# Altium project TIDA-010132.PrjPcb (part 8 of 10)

## Sheet AFE2-SERDES.SchDoc
size 431 x 279 mm; Date: Not shown in title block; ApprovedBy: Not shown in title block; CheckedBy: Not shown in title block; Author: Not shown in title block; CompanyName: Not shown in title block; DrawnBy: Avinash N; Engineer: Not shown in title block; Organization: Not shown in title block; Address1: Not shown in title block; Address2: Not shown in title block; Address3: Not shown in title block; Address4: Not shown in title block; DocumentNumber: 1; Revision: Use project parameter SCH_Rev; SheetNumber: 19; SheetTotal: 32; PageSetup: Record=PageOptions¦CenterHorizontal=True¦CenterVertical=True¦PrintScale=1.00¦XCorrection=1.00¦YCorrection=1.00¦PrintKind=0¦BorderSize=5000000¦LeftOffset=0¦BottomOffset=0¦Orientation=2¦PaperLength=1000¦PaperWidth=1000¦Scale=100¦PaperSource=15¦PrintQuality=600¦MediaType=1¦DitherType=10¦PaperKind=Letter¦PrintScaleMode=1
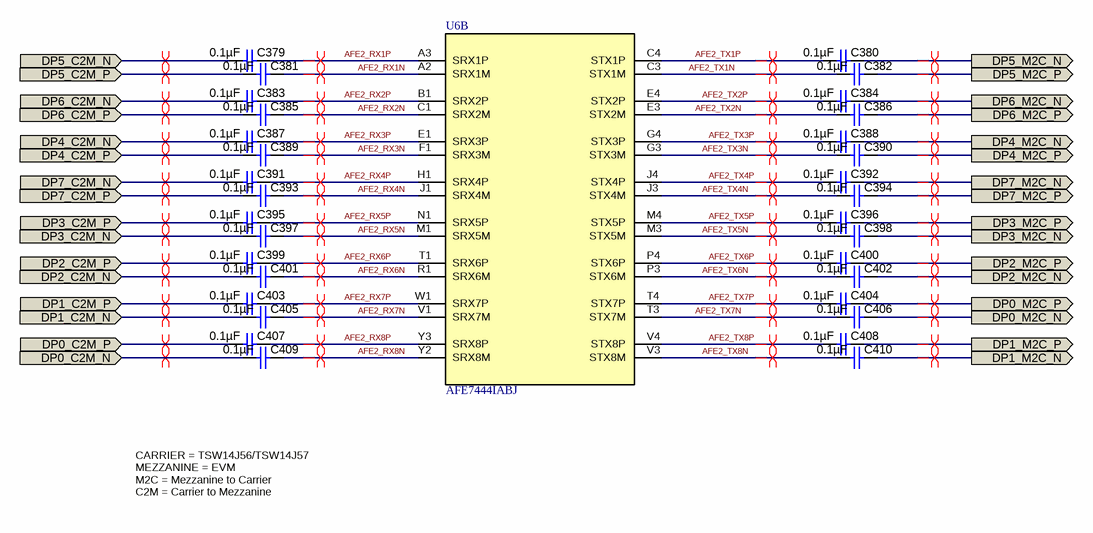
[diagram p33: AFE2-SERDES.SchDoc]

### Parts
C379  ValueDisplayed: 0.1µF  [0201_afe]  (hidden comment: 530Z104KT10T)
C380  ValueDisplayed: 0.1µF  [0201_afe]  (hidden comment: 530Z104KT10T)
C381  ValueDisplayed: 0.1µF  [0201_afe]  (hidden comment: 530Z104KT10T)
C382  ValueDisplayed: 0.1µF  [0201_afe]  (hidden comment: 530Z104KT10T)
C383  ValueDisplayed: 0.1µF  [0201_afe]  (hidden comment: 530Z104KT10T)
C384  ValueDisplayed: 0.1µF  [0201_afe]  (hidden comment: 530Z104KT10T)
C385  ValueDisplayed: 0.1µF  [0201_afe]  (hidden comment: 530Z104KT10T)
C386  ValueDisplayed: 0.1µF  [0201_afe]  (hidden comment: 530Z104KT10T)
C387  ValueDisplayed: 0.1µF  [0201_afe]  (hidden comment: 530Z104KT10T)
C388  ValueDisplayed: 0.1µF  [0201_afe]  (hidden comment: 530Z104KT10T)
C389  ValueDisplayed: 0.1µF  [0201_afe]  (hidden comment: 530Z104KT10T)
C390  ValueDisplayed: 0.1µF  [0201_afe]  (hidden comment: 530Z104KT10T)
C391  ValueDisplayed: 0.1µF  [0201_afe]  (hidden comment: 530Z104KT10T)
C392  ValueDisplayed: 0.1µF  [0201_afe]  (hidden comment: 530Z104KT10T)
C393  ValueDisplayed: 0.1µF  [0201_afe]  (hidden comment: 530Z104KT10T)
C394  ValueDisplayed: 0.1µF  [0201_afe]  (hidden comment: 530Z104KT10T)
C395  ValueDisplayed: 0.1µF  [0201_afe]  (hidden comment: 530Z104KT10T)
C396  ValueDisplayed: 0.1µF  [0201_afe]  (hidden comment: 530Z104KT10T)
C397  ValueDisplayed: 0.1µF  [0201_afe]  (hidden comment: 530Z104KT10T)
C398  ValueDisplayed: 0.1µF  [0201_afe]  (hidden comment: 530Z104KT10T)
C399  ValueDisplayed: 0.1µF  [0201_afe]  (hidden comment: 530Z104KT10T)
C400  ValueDisplayed: 0.1µF  [0201_afe]  (hidden comment: 530Z104KT10T)
C401  ValueDisplayed: 0.1µF  [0201_afe]  (hidden comment: 530Z104KT10T)
C402  ValueDisplayed: 0.1µF  [0201_afe]  (hidden comment: 530Z104KT10T)
C403  ValueDisplayed: 0.1µF  [0201_afe]  (hidden comment: 530Z104KT10T)
C404  ValueDisplayed: 0.1µF  [0201_afe]  (hidden comment: 530Z104KT10T)
C405  ValueDisplayed: 0.1µF  [0201_afe]  (hidden comment: 530Z104KT10T)
C406  ValueDisplayed: 0.1µF  [0201_afe]  (hidden comment: 530Z104KT10T)
C407  ValueDisplayed: 0.1µF  [0201_afe]  (hidden comment: 530Z104KT10T)
C408  ValueDisplayed: 0.1µF  [0201_afe]  (hidden comment: 530Z104KT10T)
C409  ValueDisplayed: 0.1µF  [0201_afe]  (hidden comment: 530Z104KT10T)
C410  ValueDisplayed: 0.1µF  [0201_afe]  (hidden comment: 530Z104KT10T)
U6  AFE7444IABJ  [ABJ0400A]  (part B of 6)

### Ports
DP0_C2M_N (in), DP0_C2M_P (in), DP0_M2C_N (out), DP0_M2C_P (out), DP1_C2M_N (in), DP1_C2M_P (in), DP1_M2C_N (out), DP1_M2C_P (out), DP2_C2M_N (in), DP2_C2M_P (in), DP2_M2C_N (out), DP2_M2C_P (out), DP3_C2M_N (in), DP3_C2M_P (in), DP3_M2C_N (out), DP3_M2C_P (out), DP4_C2M_N (in), DP4_C2M_P (in), DP4_M2C_N (out), DP4_M2C_P (out), DP5_C2M_N (in), DP5_C2M_P (in), DP5_M2C_N (out), DP5_M2C_P (out), DP6_C2M_N (in), DP6_C2M_P (in), DP6_M2C_N (out), DP6_M2C_P (out), DP7_C2M_N (in), DP7_C2M_P (in), DP7_M2C_N (out), DP7_M2C_P (out)

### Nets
AFE2_RX1N: C381.2 U6.A2(SRX1M)
AFE2_RX1P: C379.2 U6.A3(SRX1P)
AFE2_RX2N: C385.2 U6.C1(SRX2M)
AFE2_RX2P: C383.2 U6.B1(SRX2P)
AFE2_RX3N: C389.2 U6.F1(SRX3M)
AFE2_RX3P: C387.2 U6.E1(SRX3P)
AFE2_RX4N: C393.2 U6.J1(SRX4M)
AFE2_RX4P: C391.2 U6.H1(SRX4P)
AFE2_RX5N: C397.2 U6.M1(SRX5M)
AFE2_RX5P: C395.2 U6.N1(SRX5P)
AFE2_RX6N: C401.2 U6.R1(SRX6M)
AFE2_RX6P: C399.2 U6.T1(SRX6P)
AFE2_RX7N: C405.2 U6.V1(SRX7M)
AFE2_RX7P: C403.2 U6.W1(SRX7P)
AFE2_RX8N: C409.2 U6.Y2(SRX8M)
AFE2_RX8P: C407.2 U6.Y3(SRX8P)
AFE2_TX1N: C382.1 U6.C3(STX1M)
AFE2_TX1P: C380.1 U6.C4(STX1P)
AFE2_TX2N: C386.1 U6.E3(STX2M)
AFE2_TX2P: C384.1 U6.E4(STX2P)
AFE2_TX3N: C390.1 U6.G3(STX3M)
AFE2_TX3P: C388.1 U6.G4(STX3P)
AFE2_TX4N: C394.1 U6.J3(STX4M)
AFE2_TX4P: C392.1 U6.J4(STX4P)
AFE2_TX5N: C398.1 U6.M3(STX5M)
AFE2_TX5P: C396.1 U6.M4(STX5P)
AFE2_TX6N: C402.1 U6.P3(STX6M)
AFE2_TX6P: C400.1 U6.P4(STX6P)
AFE2_TX7N: C406.1 U6.T3(STX7M)
AFE2_TX7P: C404.1 U6.T4(STX7P)
AFE2_TX8N: C410.1 U6.V3(STX8M)
AFE2_TX8P: C408.1 U6.V4(STX8P)
DP0_C2M_N: C409.1 ; port DP0_C2M_N
DP0_C2M_P: C407.1 ; port DP0_C2M_P
DP0_M2C_N: C406.2 ; port DP0_M2C_N
DP0_M2C_P: C404.2 ; port DP0_M2C_P
DP1_C2M_N: C405.1 ; port DP1_C2M_N
DP1_C2M_P: C403.1 ; port DP1_C2M_P
DP1_M2C_N: C410.2 ; port DP1_M2C_N
DP1_M2C_P: C408.2 ; port DP1_M2C_P
DP2_C2M_N: C401.1 ; port DP2_C2M_N
DP2_C2M_P: C399.1 ; port DP2_C2M_P
DP2_M2C_N: C402.2 ; port DP2_M2C_N
DP2_M2C_P: C400.2 ; port DP2_M2C_P
DP3_C2M_N: C397.1 ; port DP3_C2M_N
DP3_C2M_P: C395.1 ; port DP3_C2M_P
DP3_M2C_N: C398.2 ; port DP3_M2C_N
DP3_M2C_P: C396.2 ; port DP3_M2C_P
DP4_C2M_N: C387.1 ; port DP4_C2M_N
DP4_C2M_P: C389.1 ; port DP4_C2M_P
DP4_M2C_N: C388.2 ; port DP4_M2C_N
DP4_M2C_P: C390.2 ; port DP4_M2C_P
DP5_C2M_N: C379.1 ; port DP5_C2M_N
DP5_C2M_P: C381.1 ; port DP5_C2M_P
DP5_M2C_N: C380.2 ; port DP5_M2C_N
DP5_M2C_P: C382.2 ; port DP5_M2C_P
DP6_C2M_N: C383.1 ; port DP6_C2M_N
DP6_C2M_P: C385.1 ; port DP6_C2M_P
DP6_M2C_N: C384.2 ; port DP6_M2C_N
DP6_M2C_P: C386.2 ; port DP6_M2C_P
DP7_C2M_N: C391.1 ; port DP7_C2M_N
DP7_C2M_P: C393.1 ; port DP7_C2M_P
DP7_M2C_N: C392.2 ; port DP7_M2C_N
DP7_M2C_P: C394.2 ; port DP7_M2C_P

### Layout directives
differential pair: AFE2_RX1N, AFE2_RX1P, AFE2_RX2N, AFE2_RX2P, AFE2_RX3N, AFE2_RX3P, AFE2_RX4N, AFE2_RX4P, AFE2_RX5N, AFE2_RX5P, AFE2_RX6N, AFE2_RX6P, AFE2_RX7N, AFE2_RX7P, AFE2_RX8N, AFE2_RX8P, AFE2_TX1N, AFE2_TX1P, AFE2_TX2N, AFE2_TX2P, AFE2_TX3N, AFE2_TX3P, AFE2_TX4N, AFE2_TX4P, AFE2_TX5N, AFE2_TX5P, AFE2_TX6N, AFE2_TX6P, AFE2_TX7N, AFE2_TX7P, AFE2_TX8N, AFE2_TX8P, DP0_C2M_N, DP0_C2M_P, DP0_M2C_N, DP0_M2C_P, DP1_C2M_N, DP1_C2M_P, DP1_M2C_N, DP1_M2C_P, DP2_C2M_N, DP2_C2M_P, DP2_M2C_N, DP2_M2C_P, DP3_C2M_N, DP3_C2M_P, DP3_M2C_N, DP3_M2C_P, DP4_C2M_N, DP4_C2M_P, DP4_M2C_N, DP4_M2C_P, DP5_C2M_N, DP5_C2M_P, DP5_M2C_N, DP5_M2C_P, DP6_C2M_N, DP6_C2M_P, DP6_M2C_N, DP6_M2C_P, DP7_C2M_N, DP7_C2M_P, DP7_M2C_N, DP7_M2C_P

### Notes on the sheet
- CARRIER = TSW14J56/TSW14J57
  MEZZANINE = EVM
  M2C = Mezzanine to Carrier
  C2M = Carrier to Mezzanine

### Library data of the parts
C379-C410 = 581-530Z104KTT: Multilayer Ceramic Capacitors MLCC - SMD/SMT 10volts 0.1uF 10%; Manufacturer: ATC; Polarized: N; U/M: EA; Cap_F: 0.0000001; Tolerance_%: 10; Value1: Unknown; Value2: 10V; TempCo: X7S; TaMin_C: -55; TaMax_C: 125; Cap_Case: 0201; SizeArea_mm2: 0.18; SizeAreaWB_mm2: 2.08; SizeX_mm: 0.6; SizeY_mm: 0.3; SizeZ_mm: 0.26; AEC Category: Q200
U6 = CMP-0084351-1: Quad-Channel RF Sampling Transceiver with 14-bit 9-GSPS DACs and 14-bit 3-GSPS ADCs, ABJ0400A (DSBGA-400); Manufacturer: Texas Instruments; SizeY_mm: 17; AEC Qualified: N; CompType: IC; SizeZ_mm: 2.65; SizeAreaWB_mm2: 361; AEC Category: Q200; SizeArea_mm2: 289

## Sheet AFE2-PROGRAMMING INTERFACE.SchDoc
size 431 x 279 mm; Date: Not shown in title block; ApprovedBy: Not shown in title block; CheckedBy: Not shown in title block; Author: Not shown in title block; CompanyName: Not shown in title block; DrawnBy: Avinash N; Engineer: Not shown in title block; Organization: Not shown in title block; Address1: Not shown in title block; Address2: Not shown in title block; Address3: Not shown in title block; Address4: Not shown in title block; DocumentNumber: 1; Revision: Use project parameter SCH_Rev; SheetNumber: 20; SheetTotal: 32; PageSetup: Record=PageOptions¦CenterHorizontal=True¦CenterVertical=True¦PrintScale=1.00¦XCorrection=1.00¦YCorrection=1.00¦PrintKind=0¦BorderSize=5000000¦LeftOffset=0¦BottomOffset=0¦Orientation=2¦PaperLength=1000¦PaperWidth=1000¦Scale=100¦PaperSource=15¦PrintQuality=600¦MediaType=1¦DitherType=10¦PaperKind=Letter¦PrintScaleMode=1
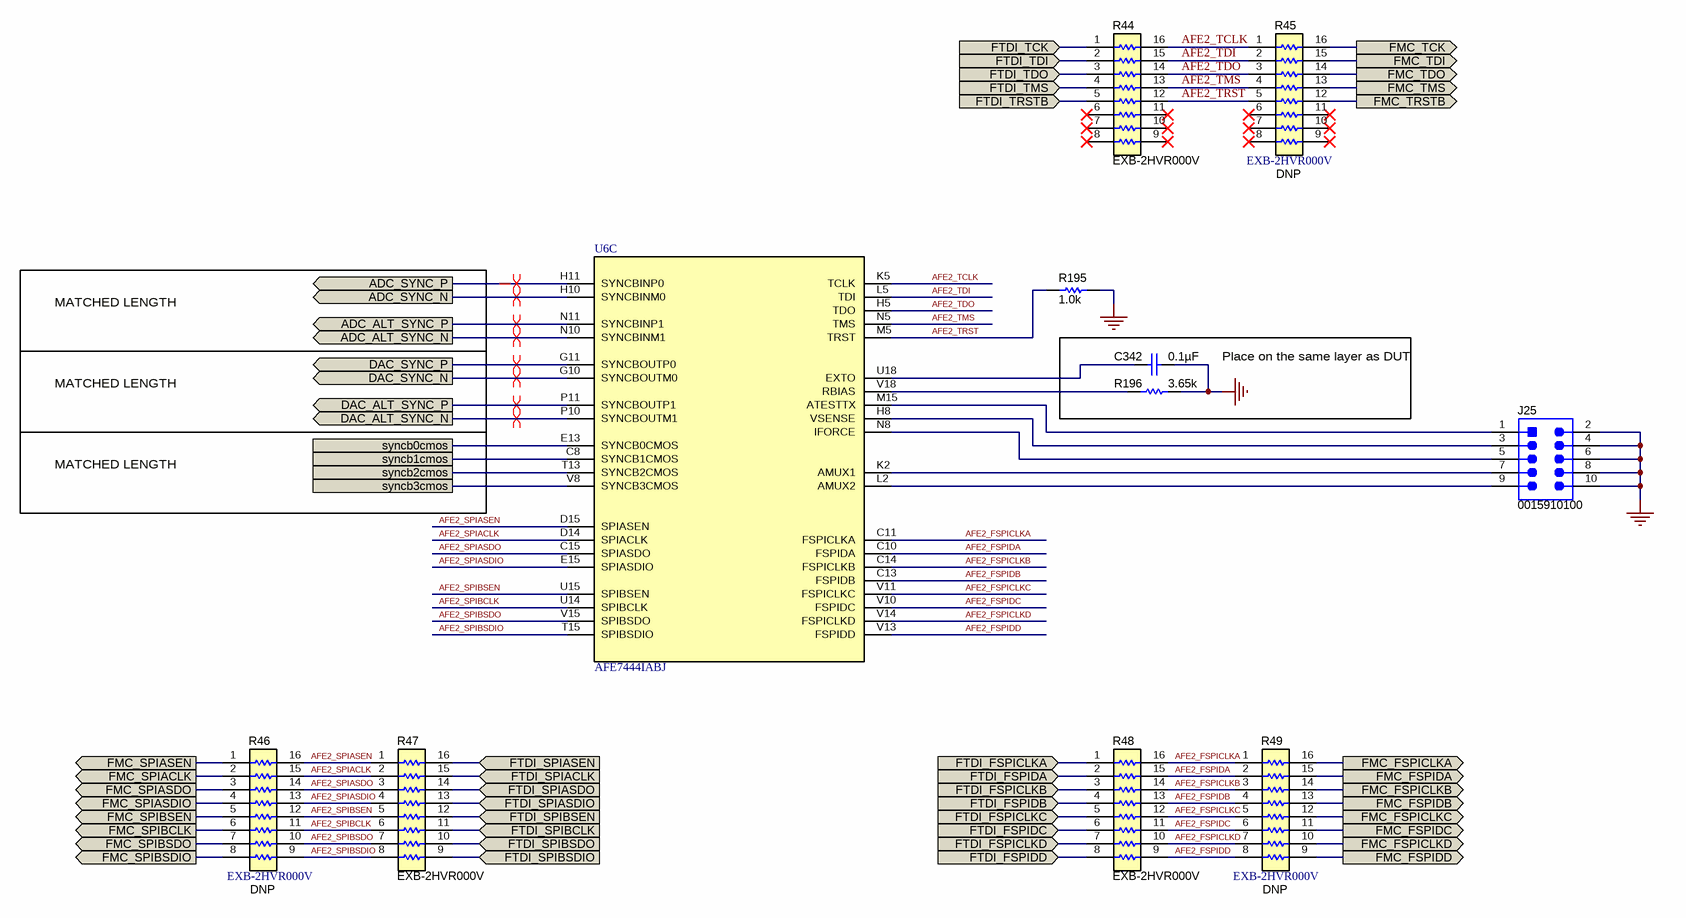
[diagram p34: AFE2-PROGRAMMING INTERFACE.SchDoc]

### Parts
C342  ValueDisplayed: 0.1µF  [0201]  (hidden comment: GRM033C71A104KE14D)
J25  0015910100  [Molex_0015910100]
R44  EXB-2HVR000V  [RESCAXS_EXB-2HV]
R45  DNP  PartNumber: EXB-2HVR000V  [RESCAXS_EXB-2HV]
R46  DNP  PartNumber: EXB-2HVR000V  [RESCAXS_EXB-2HV]
R47  EXB-2HVR000V  [RESCAXS_EXB-2HV]
R48  EXB-2HVR000V  [RESCAXS_EXB-2HV]
R49  DNP  PartNumber: EXB-2HVR000V  [RESCAXS_EXB-2HV]
R195  ValueDisplayed: 1.0k  [0402]  (hidden comment: CRCW04021K00JNED)
R196  ValueDisplayed: 3.65k  [0402]  (hidden comment: ERJ-2RKF3651X)
U6  AFE7444IABJ  [ABJ0400A]  (part C of 6)

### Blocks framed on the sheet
Place on the same layer as DUT: C342 R196

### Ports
ADC_ALT_SYNC_N (out), ADC_ALT_SYNC_P (out), ADC_SYNC_N (out), ADC_SYNC_P (out), DAC_ALT_SYNC_N (out), DAC_ALT_SYNC_P (out), DAC_SYNC_N (out), DAC_SYNC_P (out), FMC_FSPICLKA (out), FMC_FSPICLKB (out), FMC_FSPICLKC (out), FMC_FSPICLKD (out), FMC_FSPIDA (out), FMC_FSPIDB (out), FMC_FSPIDC (out), FMC_FSPIDD (out), FMC_SPIACLK (out), FMC_SPIASDIO (out), FMC_SPIASDO (out), FMC_SPIASEN (out), FMC_SPIBCLK (out), FMC_SPIBSDIO (out), FMC_SPIBSDO (out), FMC_SPIBSEN (out), FMC_TCK (out), FMC_TDI (out), FMC_TDO (out), FMC_TMS (out), FMC_TRSTB (out), FTDI_FSPICLKA (in), FTDI_FSPICLKB (in), FTDI_FSPICLKC (in), FTDI_FSPICLKD (in), FTDI_FSPIDA (in), FTDI_FSPIDB (in), FTDI_FSPIDC (in), FTDI_FSPIDD (in), FTDI_SPIACLK (in), FTDI_SPIASDIO (in), FTDI_SPIASDO (in), FTDI_SPIASEN (in), FTDI_SPIBCLK (in), FTDI_SPIBSDIO (in), FTDI_SPIBSDO (in), FTDI_SPIBSEN (in), FTDI_TCK (in), FTDI_TDI (in), FTDI_TDO (in), FTDI_TMS (in), FTDI_TRSTB (in), syncb0cmos, syncb1cmos, syncb2cmos, syncb3cmos

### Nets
GND: C342.1 J25.2 J25.4 J25.6 J25.8 J25.10 R195.1 R196.2
ADC_ALT_SYNC_N: U6.N10(SYNCBINM1) ; port ADC_ALT_SYNC_N
ADC_ALT_SYNC_P: U6.N11(SYNCBINP1) ; port ADC_ALT_SYNC_P
ADC_SYNC_N: U6.H10(SYNCBINM0) ; port ADC_SYNC_N
ADC_SYNC_P: U6.H11(SYNCBINP0) ; port ADC_SYNC_P
AFE2_FSPICLKA: R48.16 R49.1 U6.C11(FSPICLKA)
AFE2_FSPICLKB: R48.14 R49.3 U6.C14(FSPICLKB)
AFE2_FSPICLKC: R48.12 R49.5 U6.V11(FSPICLKC)
AFE2_FSPICLKD: R48.10 R49.7 U6.V14(FSPICLKD)
AFE2_FSPIDA: R48.15 R49.2 U6.C10(FSPIDA)
AFE2_FSPIDB: R48.13 R49.4 U6.C13(FSPIDB)
AFE2_FSPIDC: R48.11 R49.6 U6.V10(FSPIDC)
AFE2_FSPIDD: R48.9 R49.8 U6.V13(FSPIDD)
AFE2_SPIACLK: R46.15 R47.2 U6.D14(SPIACLK)
AFE2_SPIASDIO: R46.13 R47.4 U6.E15(SPIASDIO)
AFE2_SPIASDO: R46.14 R47.3 U6.C15(SPIASDO)
AFE2_SPIASEN: R46.16 R47.1 U6.D15(SPIASEN)
AFE2_SPIBCLK: R46.11 R47.6 U6.U14(SPIBCLK)
AFE2_SPIBSDIO: R46.9 R47.8 U6.T15(SPIBSDIO)
AFE2_SPIBSDO: R46.10 R47.7 U6.V15(SPIBSDO)
AFE2_SPIBSEN: R46.12 R47.5 U6.U15(SPIBSEN)
AFE2_TCLK: R44.16 R45.1 U6.K5(TCLK)
AFE2_TDI: R44.15 R45.2 U6.L5(TDI)
AFE2_TDO: R44.14 R45.3 U6.H5(TDO)
AFE2_TMS: R44.13 R45.4 U6.N5(TMS)
AFE2_TRST: R44.12 R45.5 R195.2 U6.M5(TRST)
DAC_ALT_SYNC_N: U6.P10(SYNCBOUTM1) ; port DAC_ALT_SYNC_N
DAC_ALT_SYNC_P: U6.P11(SYNCBOUTP1) ; port DAC_ALT_SYNC_P
DAC_SYNC_N: U6.G10(SYNCBOUTM0) ; port DAC_SYNC_N
DAC_SYNC_P: U6.G11(SYNCBOUTP0) ; port DAC_SYNC_P
FMC_FSPICLKA: R49.16 ; port FMC_FSPICLKA
FMC_FSPICLKB: R49.14 ; port FMC_FSPICLKB
FMC_FSPICLKC: R49.12 ; port FMC_FSPICLKC
FMC_FSPICLKD: R49.10 ; port FMC_FSPICLKD
FMC_FSPIDA: R49.15 ; port FMC_FSPIDA
FMC_FSPIDB: R49.13 ; port FMC_FSPIDB
FMC_FSPIDC: R49.11 ; port FMC_FSPIDC
FMC_FSPIDD: R49.9 ; port FMC_FSPIDD
FMC_SPIACLK: R46.2 ; port FMC_SPIACLK
FMC_SPIASDIO: R46.4 ; port FMC_SPIASDIO
FMC_SPIASDO: R46.3 ; port FMC_SPIASDO
FMC_SPIASEN: R46.1 ; port FMC_SPIASEN
FMC_SPIBCLK: R46.6 ; port FMC_SPIBCLK
FMC_SPIBSDIO: R46.8 ; port FMC_SPIBSDIO
FMC_SPIBSDO: R46.7 ; port FMC_SPIBSDO
FMC_SPIBSEN: R46.5 ; port FMC_SPIBSEN
FMC_TCK: R45.16 ; port FMC_TCK
FMC_TDI: R45.15 ; port FMC_TDI
FMC_TDO: R45.14 ; port FMC_TDO
FMC_TMS: R45.13 ; port FMC_TMS
FMC_TRSTB: R45.12 ; port FMC_TRSTB
FTDI_FSPICLKA: R48.1 ; port FTDI_FSPICLKA
FTDI_FSPICLKB: R48.3 ; port FTDI_FSPICLKB
FTDI_FSPICLKC: R48.5 ; port FTDI_FSPICLKC
FTDI_FSPICLKD: R48.7 ; port FTDI_FSPICLKD
FTDI_FSPIDA: R48.2 ; port FTDI_FSPIDA
FTDI_FSPIDB: R48.4 ; port FTDI_FSPIDB
FTDI_FSPIDC: R48.6 ; port FTDI_FSPIDC
FTDI_FSPIDD: R48.8 ; port FTDI_FSPIDD
FTDI_SPIACLK: R47.15 ; port FTDI_SPIACLK
FTDI_SPIASDIO: R47.13 ; port FTDI_SPIASDIO
FTDI_SPIASDO: R47.14 ; port FTDI_SPIASDO
FTDI_SPIASEN: R47.16 ; port FTDI_SPIASEN
FTDI_SPIBCLK: R47.11 ; port FTDI_SPIBCLK
FTDI_SPIBSDIO: R47.9 ; port FTDI_SPIBSDIO
FTDI_SPIBSDO: R47.10 ; port FTDI_SPIBSDO
FTDI_SPIBSEN: R47.12 ; port FTDI_SPIBSEN
FTDI_TCK: R44.1 ; port FTDI_TCK
FTDI_TDI: R44.2 ; port FTDI_TDI
FTDI_TDO: R44.3 ; port FTDI_TDO
FTDI_TMS: R44.4 ; port FTDI_TMS
FTDI_TRSTB: R44.5 ; port FTDI_TRSTB
syncb0cmos: U6.E13(SYNCB0CMOS) ; port syncb0cmos
syncb1cmos: U6.C8(SYNCB1CMOS) ; port syncb1cmos
syncb2cmos: U6.T13(SYNCB2CMOS) ; port syncb2cmos
syncb3cmos: U6.V8(SYNCB3CMOS) ; port syncb3cmos
NetC342_2: C342.2 U6.U18(EXTO)
NetJ25_1: J25.1 U6.M15(ATESTTX)
NetJ25_3: J25.3 U6.H8(VSENSE)
NetJ25_5: J25.5 U6.N8(IFORCE)
NetJ25_7: J25.7 U6.K2(AMUX1)
NetJ25_9: J25.9 U6.L2(AMUX2)
NetR196_1: R196.1 U6.V18(RBIAS)

Not connected (* = marked no-connect by the designer): R44 6* 7* 8* 9* 10* 11*; R45 6* 7* 8* 9* 10* 11*

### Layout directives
differential pair: ADC_ALT_SYNC_N, ADC_ALT_SYNC_P, ADC_SYNC_N, ADC_SYNC_P, DAC_ALT_SYNC_N, DAC_ALT_SYNC_P, DAC_SYNC_N, DAC_SYNC_P

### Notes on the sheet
- MATCHED LENGTH

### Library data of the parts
C342 = GRM033C71A104KE14D: CAP, CERM, 0.1 µF, 10 V,+/- 10%, X7S, 0201; Manufacturer: MuRata; Polarized: N; CompType: Capacitor; Value: 0.1uF; U/M: EA; Cap_F: 0.0000001; Tolerance_%: 10; Value1: Unknown; Value2: 10V; TaMin_C: -55; TaMax_C: 125; SizeArea_mm2: 0.18; SizeAreaWB_mm2: 2.08; SizeX_mm: 0.6; SizeY_mm: 0.3; SizeZ_mm: 0.26; AEC Category: Q200
J25 = 0015910100: Header, 100mil, 5x2, SMT; Manufacturer: Molex; SymbolCreator: a0412235; Green_Lifecycle: Active; Green_REACh: Passed
R44-R49 = CMP-0015352-2: RES, 0, 5%, 0.0625 W, Resistor Array - 8x1; Manufacturer: Panasonic; Power_W: 62.5mW; TempCo: ppm/C; Value_Code: 0000; U/M: EA; Value: 0; EIA_Code: E24; AEC Category: Q200
R195 = CRCW04021K00JNED: RES, 1.0 k, 5%, 0.063 W, 0402; Manufacturer: Vishay-Dale; CompType: Resistor; Value: 1.0k; Res_ohm: 1000; Value_Code: 1k00; Tolerance_%: 5; Power_W: 0.063; Value2: 0.063W; VDC_V: 50; TempCo: 200 ppm/C; SizeArea_mm2: 0.5; SizeX_mm: 1; SizeZ_mm: 0.6; EIA_Code: E24; U/M: EA; AEC Category: Q200; Green_Lifecycle: Active; Green_REACh: Passed
R196 = ERJ-2RKF3651X: RES, 3.65 k, 1%, 0.1 W, AEC-Q200 Grade 0, 0402; Manufacturer: Panasonic; CompType: Resistor; Value: 3.65k; Res_ohm: 3650; Value_Code: 3k65; Tolerance_%: 1; Power_W: 0.1; Value2: 0.1W; VDC_V: 50; TempCo: 100 ppm/C; SizeArea_mm2: 0.5; SizeZ_mm: 0.6; EIA_Code: E96; U/M: EA; AEC Category: Q200; AEC Qualified: Y; AEC Grade: 0
U6 = CMP-0084351-1: as U6 on sheet AFE2-SERDES

## Sheet AFE2-GPIOs.SchDoc
size 431 x 279 mm; Date: Not shown in title block; ApprovedBy: Not shown in title block; CheckedBy: Not shown in title block; Author: Not shown in title block; CompanyName: Not shown in title block; DrawnBy: Avinash N; Engineer: Not shown in title block; Organization: Not shown in title block; Address1: Not shown in title block; Address2: Not shown in title block; Address3: Not shown in title block; Address4: Not shown in title block; DocumentNumber: 1; Revision: Use project parameter SCH_Rev; SheetNumber: 21; SheetTotal: 32; PageSetup: Record=PageOptions¦CenterHorizontal=True¦CenterVertical=True¦PrintScale=1.00¦XCorrection=1.00¦YCorrection=1.00¦PrintKind=0¦BorderSize=5000000¦LeftOffset=0¦BottomOffset=0¦Orientation=2¦PaperLength=1000¦PaperWidth=1000¦Scale=100¦PaperSource=15¦PrintQuality=600¦MediaType=1¦DitherType=10¦PaperKind=Letter¦PrintScaleMode=1
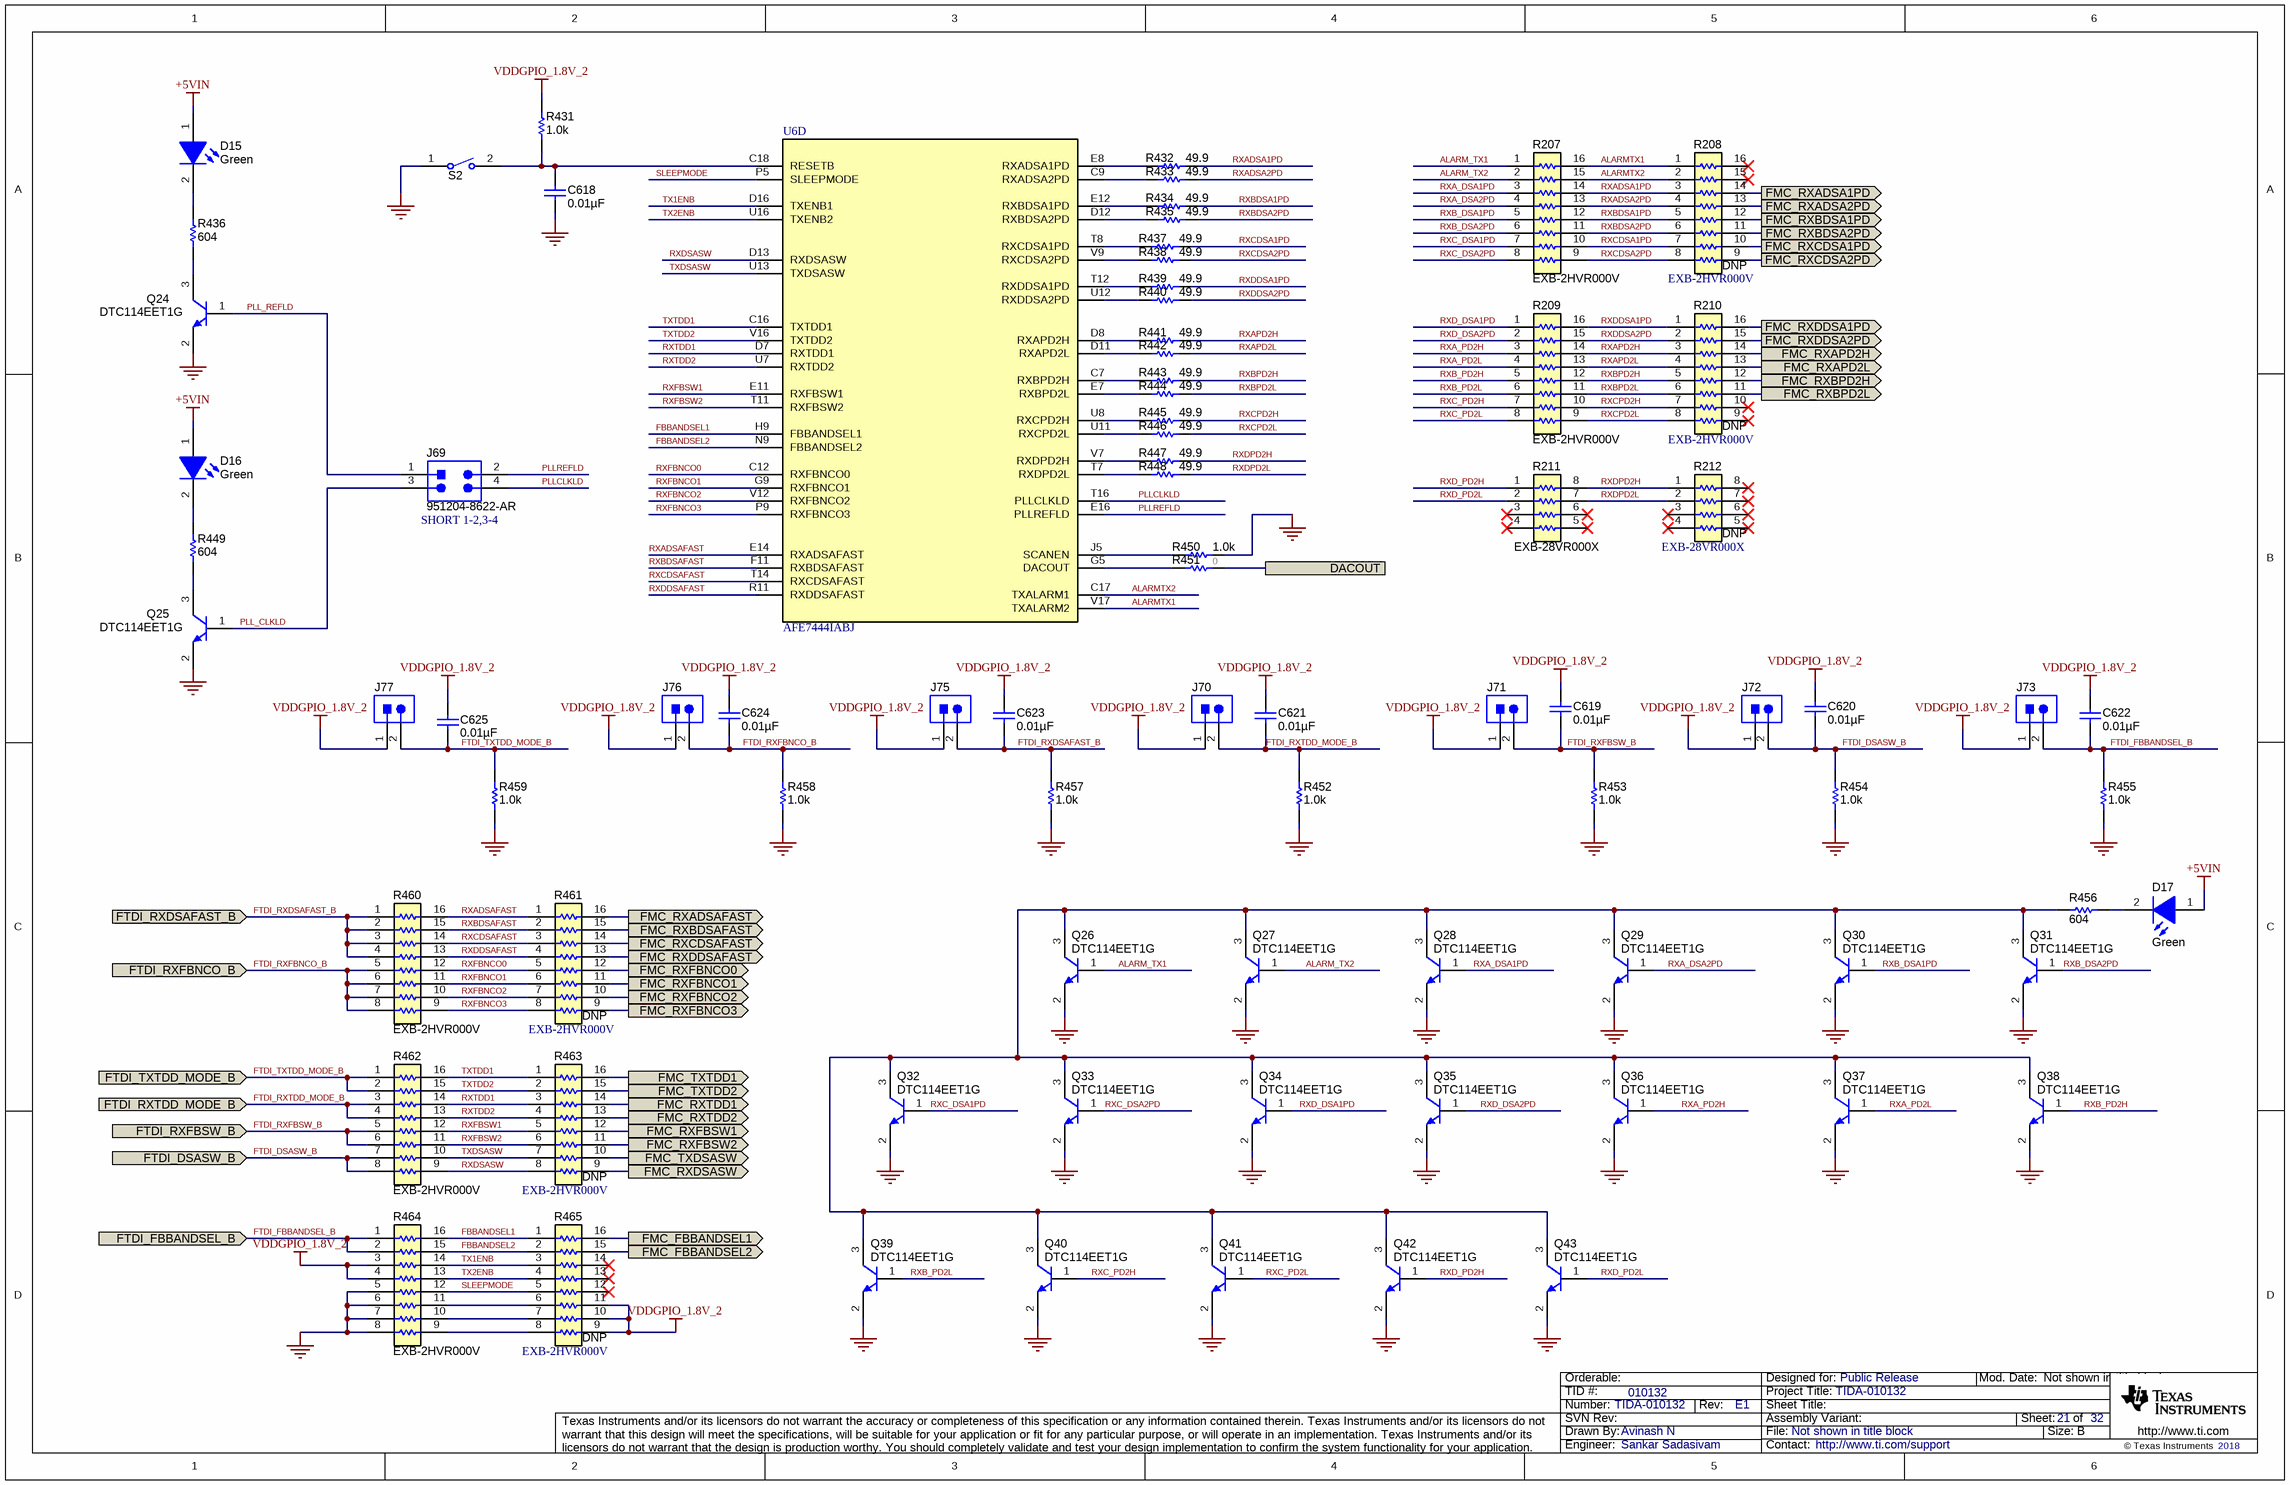
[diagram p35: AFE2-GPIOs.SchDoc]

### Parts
C618  ValueDisplayed: 0.01µF  [0402]  (hidden comment: 0402ZC103KAT2A)
C619  ValueDisplayed: 0.01µF  [0402]  (hidden comment: 0402ZC103KAT2A)
C620  ValueDisplayed: 0.01µF  [0402]  (hidden comment: 0402ZC103KAT2A)
C621  ValueDisplayed: 0.01µF  [0402]  (hidden comment: 0402ZC103KAT2A)
C622  ValueDisplayed: 0.01µF  [0402]  (hidden comment: 0402ZC103KAT2A)
C623  ValueDisplayed: 0.01µF  [0402]  (hidden comment: 0402ZC103KAT2A)
C624  ValueDisplayed: 0.01µF  [0402]  (hidden comment: 0402ZC103KAT2A)
C625  ValueDisplayed: 0.01µF  [0402]  (hidden comment: 0402ZC103KAT2A)
D15  value Green  [LTST-C191_Green]  (hidden comment: LTST-C191TGKT)
D16  value Green  [LTST-C191_Green]  (hidden comment: LTST-C191TGKT)
D17  value Green  [LTST-C191_Green]  (hidden comment: LTST-C191TGKT)
J69  951204-8622-AR  [3M_951204-8622]
J70  TSW-102-07-T-S  [Samtec_TSW-102-07-T-S]  (value not drawn)
J71  TSW-102-07-T-S  [Samtec_TSW-102-07-T-S]  (value not drawn)
J72  TSW-102-07-T-S  [Samtec_TSW-102-07-T-S]  (value not drawn)
J73  TSW-102-07-T-S  [Samtec_TSW-102-07-T-S]  (value not drawn)
J75  TSW-102-07-T-S  [Samtec_TSW-102-07-T-S]  (value not drawn)
J76  TSW-102-07-T-S  [Samtec_TSW-102-07-T-S]  (value not drawn)
J77  TSW-102-07-T-S  [Samtec_TSW-102-07-T-S]  (value not drawn)
Q24  DTC114EET1G  [SOT-416]
Q25  DTC114EET1G  [SOT-416]
Q26  DTC114EET1G  [SOT-416]
Q27  DTC114EET1G  [SOT-416]
Q28  DTC114EET1G  [SOT-416]
Q29  DTC114EET1G  [SOT-416]
Q30  DTC114EET1G  [SOT-416]
Q31  DTC114EET1G  [SOT-416]
Q32  DTC114EET1G  [SOT-416]
Q33  DTC114EET1G  [SOT-416]
Q34  DTC114EET1G  [SOT-416]
Q35  DTC114EET1G  [SOT-416]
Q36  DTC114EET1G  [SOT-416]
Q37  DTC114EET1G  [SOT-416]
Q38  DTC114EET1G  [SOT-416]
Q39  DTC114EET1G  [SOT-416]
Q40  DTC114EET1G  [SOT-416]
Q41  DTC114EET1G  [SOT-416]
Q42  DTC114EET1G  [SOT-416]
Q43  DTC114EET1G  [SOT-416]
R207  EXB-2HVR000V  [RESCAXS_EXB-2HV]
R208  DNP  PartNumber: EXB-2HVR000V  [RESCAXS_EXB-2HV]
R209  EXB-2HVR000V  [RESCAXS_EXB-2HV]
R210  DNP  PartNumber: EXB-2HVR000V  [RESCAXS_EXB-2HV]
R211  EXB-28VR000X  [0804-8]
R212  DNP  PartNumber: EXB-28VR000X  [0804-8]
R431  ValueDisplayed: 1.0k  [0402]  (hidden comment: CRCW04021K00JNED)
R432  ValueDisplayed: 49.9  [0402]  (hidden comment: ERJ-2RKF49R9X)
R433  ValueDisplayed: 49.9  [0402]  (hidden comment: ERJ-2RKF49R9X)
R434  ValueDisplayed: 49.9  [0402]  (hidden comment: ERJ-2RKF49R9X)
R435  ValueDisplayed: 49.9  [0402]  (hidden comment: ERJ-2RKF49R9X)
R436  ValueDisplayed: 604  [0402]  (hidden comment: CRCW0402604RFKED)
R437  ValueDisplayed: 49.9  [0402]  (hidden comment: ERJ-2RKF49R9X)
R438  ValueDisplayed: 49.9  [0402]  (hidden comment: ERJ-2RKF49R9X)
R439  ValueDisplayed: 49.9  [0402]  (hidden comment: ERJ-2RKF49R9X)
R440  ValueDisplayed: 49.9  [0402]  (hidden comment: ERJ-2RKF49R9X)
R441  ValueDisplayed: 49.9  [0402]  (hidden comment: ERJ-2RKF49R9X)
R442  ValueDisplayed: 49.9  [0402]  (hidden comment: ERJ-2RKF49R9X)
R443  ValueDisplayed: 49.9  [0402]  (hidden comment: ERJ-2RKF49R9X)
R444  ValueDisplayed: 49.9  [0402]  (hidden comment: ERJ-2RKF49R9X)
R445  ValueDisplayed: 49.9  [0402]  (hidden comment: ERJ-2RKF49R9X)
R446  ValueDisplayed: 49.9  [0402]  (hidden comment: ERJ-2RKF49R9X)
R447  ValueDisplayed: 49.9  [0402]  (hidden comment: ERJ-2RKF49R9X)
R448  ValueDisplayed: 49.9  [0402]  (hidden comment: ERJ-2RKF49R9X)
R449  ValueDisplayed: 604  [0402]  (hidden comment: CRCW0402604RFKED)
R450  ValueDisplayed: 1.0k  [0402]  (hidden comment: CRCW04021K00JNED)
R451  ValueDisplayed: 0  [0603]  (hidden comment: CRCW06030000Z0EA)
R452  ValueDisplayed: 1.0k  [0402]  (hidden comment: CRCW04021K00JNED)
R453  ValueDisplayed: 1.0k  [0402]  (hidden comment: CRCW04021K00JNED)
R454  ValueDisplayed: 1.0k  [0402]  (hidden comment: CRCW04021K00JNED)
R455  ValueDisplayed: 1.0k  [0402]  (hidden comment: CRCW04021K00JNED)
R456  ValueDisplayed: 604  [0402]  (hidden comment: CRCW0402604RFKED)
R457  ValueDisplayed: 1.0k  [0402]  (hidden comment: CRCW04021K00JNED)
R458  ValueDisplayed: 1.0k  [0402]  (hidden comment: CRCW04021K00JNED)
R459  ValueDisplayed: 1.0k  [0402]  (hidden comment: CRCW04021K00JNED)
R460  EXB-2HVR000V  [RESCAXS_EXB-2HV]
R461  DNP  PartNumber: EXB-2HVR000V  [RESCAXS_EXB-2HV]
R462  EXB-2HVR000V  [RESCAXS_EXB-2HV]
R463  DNP  PartNumber: EXB-2HVR000V  [RESCAXS_EXB-2HV]
R464  EXB-2HVR000V  [RESCAXS_EXB-2HV]
R465  DNP  PartNumber: EXB-2HVR000V  [RESCAXS_EXB-2HV]
S2  147873-2  [SW_147873-2]  (value not drawn)
U6  AFE7444IABJ  [ABJ0400A]  (part D of 6)

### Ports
DACOUT, FMC_FBBANDSEL1 (out), FMC_FBBANDSEL2 (out), FMC_RXADSA1PD (out), FMC_RXADSA2PD (out), FMC_RXADSAFAST (out), FMC_RXAPD2H (out), FMC_RXAPD2L (out), FMC_RXBDSA1PD (out), FMC_RXBDSA2PD (out), FMC_RXBDSAFAST (out), FMC_RXBPD2H (out), FMC_RXBPD2L (out), FMC_RXCDSA1PD (out), FMC_RXCDSA2PD (out), FMC_RXCDSAFAST (out), FMC_RXDDSA1PD (out), FMC_RXDDSA2PD (out), FMC_RXDDSAFAST (out), FMC_RXDSASW (out), FMC_RXFBNCO0 (out), FMC_RXFBNCO1 (out), FMC_RXFBNCO2 (out), FMC_RXFBNCO3 (out), FMC_RXFBSW1 (out), FMC_RXFBSW2 (out), FMC_RXTDD1 (out), FMC_RXTDD2 (out), FMC_TXDSASW (out), FMC_TXTDD1 (out), FMC_TXTDD2 (out), FTDI_DSASW_B (in), FTDI_FBBANDSEL_B (in), FTDI_RXDSAFAST_B (in), FTDI_RXFBNCO_B (in), FTDI_RXFBSW_B (in), FTDI_RXTDD_MODE_B (in), FTDI_TXTDD_MODE_B (in)

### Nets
+5VIN: D15.1(A) D16.1(A) D17.1(A)
GND: C618.2 Q24.2(E) Q25.2(E) Q26.2(E) Q27.2(E) Q28.2(E) Q29.2(E) Q30.2(E) Q31.2(E) Q32.2(E) Q33.2(E) Q34.2(E) Q35.2(E) Q36.2(E) Q37.2(E) Q38.2(E) Q39.2(E) Q40.2(E) Q41.2(E) Q42.2(E) Q43.2(E) R450.2 R452.1 R453.1 R454.1 R455.1 R457.1 R458.1 R459.1 R464.5 R464.6 R464.7 R464.8 S2.1
VDDGPIO_1.8V_2: C619.1 C620.1 C621.1 C622.1 C623.1 C624.1 C625.1 J70.1 J71.1 J72.1 J73.1 J75.1 J76.1 J77.1 R431.2 R464.3 R464.4 R465.9 R465.10 R465.11
ALARM_TX1: Q26.1(B) R207.1
ALARM_TX2: Q27.1(B) R207.2
ALARMTX1: R207.16 R208.1 U6.V17(TXALARM2)
ALARMTX2: R207.15 R208.2 U6.C17(TXALARM1)
DACOUT: R451.2 ; port DACOUT
FBBANDSEL1: R464.16 R465.1 U6.H9(FBBANDSEL1)
FBBANDSEL2: R464.15 R465.2 U6.N9(FBBANDSEL2)
FMC_FBBANDSEL1: R465.16 ; port FMC_FBBANDSEL1
FMC_FBBANDSEL2: R465.15 ; port FMC_FBBANDSEL2
FMC_RXADSA1PD: R208.14 ; port FMC_RXADSA1PD
FMC_RXADSA2PD: R208.13 ; port FMC_RXADSA2PD
FMC_RXADSAFAST: R461.16 ; port FMC_RXADSAFAST
FMC_RXAPD2H: R210.14 ; port FMC_RXAPD2H
FMC_RXAPD2L: R210.13 ; port FMC_RXAPD2L
FMC_RXBDSA1PD: R208.12 ; port FMC_RXBDSA1PD
FMC_RXBDSA2PD: R208.11 ; port FMC_RXBDSA2PD
FMC_RXBDSAFAST: R461.15 ; port FMC_RXBDSAFAST
FMC_RXBPD2H: R210.12 ; port FMC_RXBPD2H
FMC_RXBPD2L: R210.11 ; port FMC_RXBPD2L
FMC_RXCDSA1PD: R208.10 ; port FMC_RXCDSA1PD
FMC_RXCDSA2PD: R208.9 ; port FMC_RXCDSA2PD
FMC_RXCDSAFAST: R461.14 ; port FMC_RXCDSAFAST
FMC_RXDDSA1PD: R210.16 ; port FMC_RXDDSA1PD
FMC_RXDDSA2PD: R210.15 ; port FMC_RXDDSA2PD
FMC_RXDDSAFAST: R461.13 ; port FMC_RXDDSAFAST
FMC_RXDSASW: R463.9 ; port FMC_RXDSASW
FMC_RXFBNCO0: R461.12 ; port FMC_RXFBNCO0
FMC_RXFBNCO1: R461.11 ; port FMC_RXFBNCO1
FMC_RXFBNCO2: R461.10 ; port FMC_RXFBNCO2
FMC_RXFBNCO3: R461.9 ; port FMC_RXFBNCO3
FMC_RXFBSW1: R463.12 ; port FMC_RXFBSW1
FMC_RXFBSW2: R463.11 ; port FMC_RXFBSW2
FMC_RXTDD1: R463.14 ; port FMC_RXTDD1
FMC_RXTDD2: R463.13 ; port FMC_RXTDD2
FMC_TXDSASW: R463.10 ; port FMC_TXDSASW
FMC_TXTDD1: R463.16 ; port FMC_TXTDD1
FMC_TXTDD2: R463.15 ; port FMC_TXTDD2
FTDI_DSASW_B: C620.2 J72.2 R454.2 R462.7 R462.8 ; port FTDI_DSASW_B
FTDI_FBBANDSEL_B: C622.2 J73.2 R455.2 R464.1 R464.2 ; port FTDI_FBBANDSEL_B
FTDI_RXDSAFAST_B: C623.2 J75.2 R457.2 R460.1 R460.2 R460.3 R460.4 ; port FTDI_RXDSAFAST_B
FTDI_RXFBNCO_B: C624.2 J76.2 R458.2 R460.5 R460.6 R460.7 R460.8 ; port FTDI_RXFBNCO_B
FTDI_RXFBSW_B: C619.2 J71.2 R453.2 R462.5 R462.6 ; port FTDI_RXFBSW_B
FTDI_RXTDD_MODE_B: C621.2 J70.2 R452.2 R462.3 R462.4 ; port FTDI_RXTDD_MODE_B
FTDI_TXTDD_MODE_B: C625.2 J77.2 R459.2 R462.1 R462.2 ; port FTDI_TXTDD_MODE_B
PLL_CLKLD: J69.3 Q25.1(B)
PLL_REFLD: J69.1 Q24.1(B)
PLLCLKLD: J69.4 U6.T16(PLLCLKLD)
PLLREFLD: J69.2 U6.E16(PLLREFLD)
RXA_DSA1PD: Q28.1(B) R207.3
RXA_DSA2PD: Q29.1(B) R207.4
RXA_PD2H: Q36.1(B) R209.3
RXA_PD2L: Q37.1(B) R209.4
RXADSA1PD: R207.14 R208.3 R432.2
RXADSA2PD: R207.13 R208.4 R433.2
RXADSAFAST: R460.16 R461.1 U6.E14(RXADSAFAST)
RXAPD2H: R209.14 R210.3 R441.2
RXAPD2L: R209.13 R210.4 R442.2
RXB_DSA1PD: Q30.1(B) R207.5
RXB_DSA2PD: Q31.1(B) R207.6
RXB_PD2H: Q38.1(B) R209.5
RXB_PD2L: Q39.1(B) R209.6
RXBDSA1PD: R207.12 R208.5 R434.2
RXBDSA2PD: R207.11 R208.6 R435.2
RXBDSAFAST: R460.15 R461.2 U6.F11(RXBDSAFAST)
RXBPD2H: R209.12 R210.5 R443.2
RXBPD2L: R209.11 R210.6 R444.2
RXC_DSA1PD: Q32.1(B) R207.7
RXC_DSA2PD: Q33.1(B) R207.8
RXC_PD2H: Q40.1(B) R209.7
RXC_PD2L: Q41.1(B) R209.8
RXCDSA1PD: R207.10 R208.7 R437.2
RXCDSA2PD: R207.9 R208.8 R438.2
RXCDSAFAST: R460.14 R461.3 U6.T14(RXCDSAFAST)
RXCPD2H: R209.10 R210.7 R445.2
RXCPD2L: R209.9 R210.8 R446.2
RXD_DSA1PD: Q34.1(B) R209.1
RXD_DSA2PD: Q35.1(B) R209.2
RXD_PD2H: Q42.1(B) R211.1
RXD_PD2L: Q43.1(B) R211.2
RXDDSA1PD: R209.16 R210.1 R439.2
RXDDSA2PD: R209.15 R210.2 R440.2
RXDDSAFAST: R460.13 R461.4 U6.R11(RXDDSAFAST)
RXDPD2H: R211.8 R212.1 R447.2
RXDPD2L: R211.7 R212.2 R448.2
RXDSASW: R462.9 R463.8 U6.D13(RXDSASW)
RXFBNCO0: R460.12 R461.5 U6.C12(RXFBNCO0)
RXFBNCO1: R460.11 R461.6 U6.G9(RXFBNCO1)
RXFBNCO2: R460.10 R461.7 U6.V12(RXFBNCO2)
RXFBNCO3: R460.9 R461.8 U6.P9(RXFBNCO3)
RXFBSW1: R462.12 R463.5 U6.E11(RXFBSW1)
RXFBSW2: R462.11 R463.6 U6.T11(RXFBSW2)
RXTDD1: R462.14 R463.3 U6.D7(RXTDD1)
RXTDD2: R462.13 R463.4 U6.U7(RXTDD2)
SLEEPMODE: R464.12 R465.5 U6.P5(SLEEPMODE)
TX1ENB: R464.14 R465.3 U6.D16(TXENB1)
TX2ENB: R464.13 R465.4 U6.U16(TXENB2)
TXDSASW: R462.10 R463.7 U6.U13(TXDSASW)
TXTDD1: R462.16 R463.1 U6.C16(TXTDD1)
TXTDD2: R462.15 R463.2 U6.V16(TXTDD2)
NetC618_1: C618.1 R431.1 S2.2 U6.C18(RESETB)
NetD15_2: D15.2(K) R436.2
NetD16_2: D16.2(K) R449.2
NetD17_2: D17.2(K) R456.2
NetQ24_3: Q24.3(C) R436.1
NetQ25_3: Q25.3(C) R449.1
NetQ26_3: Q26.3(C) Q27.3(C) Q28.3(C) Q29.3(C) Q30.3(C) Q31.3(C) Q32.3(C) Q33.3(C) Q34.3(C) Q35.3(C) Q36.3(C) Q37.3(C) Q38.3(C) Q39.3(C) Q40.3(C) Q41.3(C) Q42.3(C) Q43.3(C) R456.1
NetR432_1: R432.1 U6.E8(RXADSA1PD)
NetR433_1: R433.1 U6.C9(RXADSA2PD)
NetR434_1: R434.1 U6.E12(RXBDSA1PD)
NetR435_1: R435.1 U6.D12(RXBDSA2PD)
NetR437_1: R437.1 U6.T8(RXCDSA1PD)
NetR438_1: R438.1 U6.V9(RXCDSA2PD)
NetR439_1: R439.1 U6.T12(RXDDSA1PD)
NetR440_1: R440.1 U6.U12(RXDDSA2PD)
NetR441_1: R441.1 U6.D8(RXAPD2H)
NetR442_1: R442.1 U6.D11(RXAPD2L)
NetR443_1: R443.1 U6.C7(RXBPD2H)
NetR444_1: R444.1 U6.E7(RXBPD2L)
NetR445_1: R445.1 U6.U8(RXCPD2H)
NetR446_1: R446.1 U6.U11(RXCPD2L)
NetR447_1: R447.1 U6.V7(RXDPD2H)
NetR448_1: R448.1 U6.T7(RXDPD2L)
NetR450_1: R450.1 U6.J5(SCANEN)
NetR451_1: R451.1 U6.G5(DACOUT)
NetR464_9: R464.9 R465.8
NetR464_10: R464.10 R465.7
NetR464_11: R464.11 R465.6

Not connected (* = marked no-connect by the designer): R208 15* 16*; R210 9* 10*; R211 3* 4* 5* 6*; R212 3* 4* 5* 6* 7* 8*; R465 12* 13* 14*

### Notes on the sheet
- (near J69) SHORT 1-2,3-4

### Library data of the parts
C618-C625 = 0402ZC103KAT2A: CAP, CERM, 0.01 µF, 10 V,+/- 10%, X7R, 0402; Manufacturer: AVX; Polarized: N; CompType: Capacitor; Value: 0.01uF; U/M: EA; Cap_F: 0.00000001; Tolerance_%: 10; Value2: 10V; TaMin_C: -55; TaMax_C: 125; SizeArea_mm2: 0.5; SizeAreaWB_mm2: 3; SizeX_mm: 1; SizeZ_mm: 0.6; AEC Category: Q200
D15-D17 = LTST-C191TGKT: LED, Green, SMD; Manufacturer: Lite-On; Type: InGaN; Vf_V: 3.2; Value2: 3.2V; Io_A: 0.02; Value1: W; U/M: EA
J69 = 951204-8622-AR: Header, 2mm, 2x2, Gold, TH; Manufacturer: 3M; SymbolCreator: a0412235; Pitch_mm: 2; Gender: Male; Shrouded: N; Current_A: 1; Voltage_V: 1000; Cert_UL: Y
J70-J73 J75-J77 = TSW-102-07-T-S: Header, 2.54 mm, 2x1, Tin, TH; Manufacturer: Samtec; SymbolCreator: a0412235; Pitch_mm: 2.54; Gender: Male; Shrouded: N; Row_Count: 1; Current_A: 6.3; Voltage_V: 550; Cert_CSA: Y; Green_Lifecycle: Active; Green_REACh: Passed
Q24-Q43 = DTC114EET1G, ON Semiconductor: Transistor, NPN, 50 V, 0.1 A, AEC-Q101, SOT-416; CompType: BJT; PNP: 0; NPN: 1; Vceo_V: 50; Vcesat1_V: 0.25; Value: 50 V; IcRated_A: 0.1; Value1: 0.1 A; HfeMax: 60; TaMin_C: -55; TaMax_C: 150; SizeAreaWB_mm2: 6.76; SizeArea_mm2: 2.56; SizeX_mm: 1.6; SizeZ_mm: 0.95; U/M: EA; AEC Category: Q101; AEC Qualified: Y; Green_Lifecycle: Active; Green_REACh: Passed
R207-R210 R460-R465 = CMP-0015352-2: as R44-R49 on sheet AFE2-PROGRAMMING INTERFACE
R211 R212 = CMP-0078922-1: RES ARRAY 4 RES ZERO OHM 0804; Manufacturer: Panasonic; Tolerance_%: 5%; Value_Code: 0; SizeArea_mm2: 2; AEC Qualified: Y; AEC Category: Q200; Res_ohm: 22; Value: 0; SizeZ_mm: 0.45; Green_REACh: Passed; EIA_Code: E24; TempCo: 200 ppm/C; AEC Grade: 1; Power_W: 62.5mW; VDC_V: 50V; Value2: 0.0625W; Green_Lifecycle: Active; CompType: Resistor
R431 R450 R452-R455 R457-R459 = CRCW04021K00JNED: as R195 on sheet AFE2-PROGRAMMING INTERFACE
R432-R435 R437-R448 = ERJ-2RKF49R9X: RES, 49.9, 1%, 0.1 W, AEC-Q200 Grade 0, 0402; Manufacturer: Panasonic; CompType: Resistor; Value: 49.9; Value_Code: 49R9; Tolerance_%: 1; Power_W: 0.1; Value2: 0.1W; VDC_V: 50; TempCo: 100 ppm/C; SizeArea_mm2: 0.5; SizeZ_mm: 0.6; EIA_Code: E96; U/M: EA; AEC Category: Q200; AEC Qualified: Y; AEC Grade: 0; Green_Lifecycle: Active; Green_REACh: Passed
R436 R449 R456 = CRCW0402604RFKED: RES, 604, 1%, 0.063 W, 0402; Manufacturer: Vishay-Dale; CompType: Resistor; Value: 604; Value_Code: 604R; Tolerance_%: 1; Power_W: 0.063; Value2: 0.063W; VDC_V: 50; TempCo: 100 ppm/C; SizeArea_mm2: 0.5; SizeZ_mm: 0.6; EIA_Code: E96; U/M: EA; AEC Category: Q200
R451 = CRCW06030000Z0EA: RES, 0, 5%, 0.1 W, 0603; Manufacturer: Vishay-Dale; CompType: Resistor; Tolerance_%: 5; VDC_V: 75; Power_W: 0.1; Value: 0; U/M: EA; Value_Code: 0000; Value2: 0.1W; EIA_Code: E24; TempCo: 200 ppm/C; SizeArea_mm2: 1.28; SizeX_mm: 1.6; SizeY_mm: 0.8; SizeZ_mm: 1; AEC Category: Q200
S2 = 147873-2: Switch, SPST, Off-On, 50 mA,24V, SMD; Manufacturer: TE Connectivity; SymbolCreator: a0799628; SizeAreaWB_mm2: 48.4; SizeArea_mm2: 23.8; SizeX_mm: 6.8; SizeY_mm: 3.5; SizeZ_mm: 4.65; VDC_V: 24; PositionCount: 1; CurrentRating_mA: 50
U6 = CMP-0084351-1: as U6 on sheet AFE2-SERDES

## Sheet AFE2-RX-INPUTS.SchDoc
size 431 x 279 mm; Date: Not shown in title block; ApprovedBy: Not shown in title block; CheckedBy: Not shown in title block; Author: Not shown in title block; CompanyName: Not shown in title block; DrawnBy: Avinash N; Engineer: Not shown in title block; Organization: Not shown in title block; Address1: Not shown in title block; Address2: Not shown in title block; Address3: Not shown in title block; Address4: Not shown in title block; DocumentNumber: 1; Revision: Use project parameter SCH_Rev; SheetNumber: 16; SheetTotal: 32; PageSetup: Record=PageOptions¦CenterHorizontal=True¦CenterVertical=True¦PrintScale=1.00¦XCorrection=1.00¦YCorrection=1.00¦PrintKind=0¦BorderSize=5000000¦LeftOffset=0¦BottomOffset=0¦Orientation=2¦PaperLength=1000¦PaperWidth=1000¦Scale=100¦PaperSource=15¦PrintQuality=600¦MediaType=1¦DitherType=10¦PaperKind=Letter¦PrintScaleMode=1
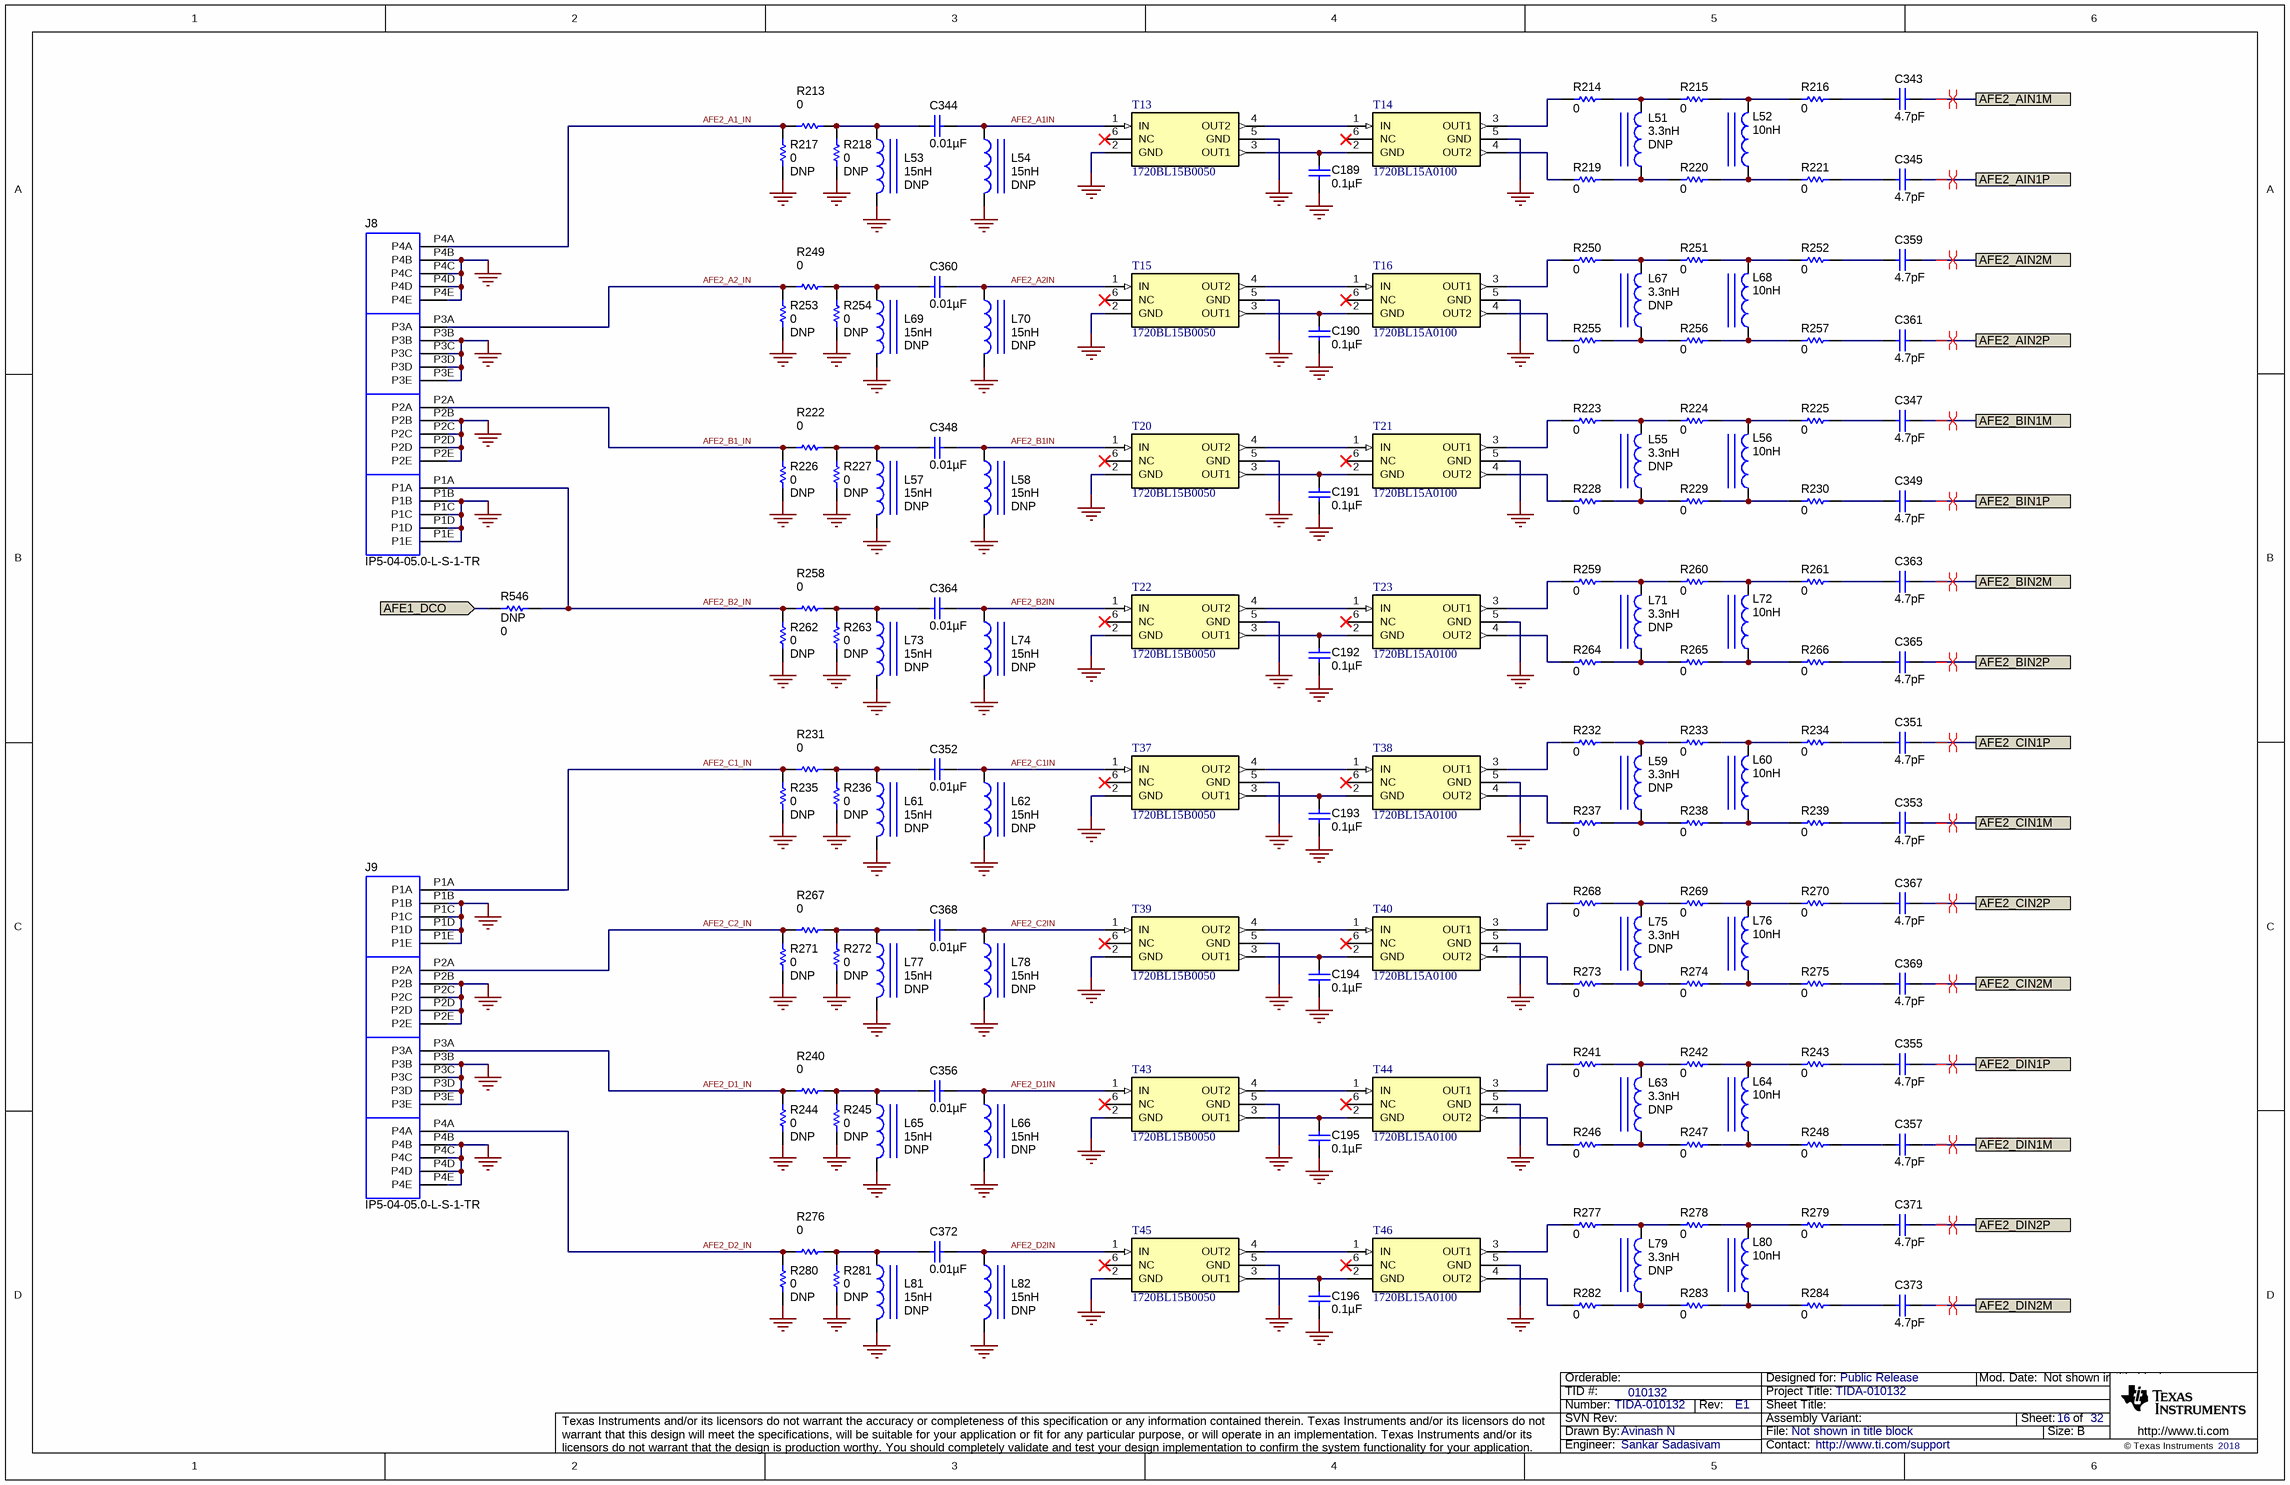
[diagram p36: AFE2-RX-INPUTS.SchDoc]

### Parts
C189  ValueDisplayed: 0.1µF  [0201]  (hidden comment: GRM033C71A104KE14D)
C190  ValueDisplayed: 0.1µF  [0201]  (hidden comment: GRM033C71A104KE14D)
C191  ValueDisplayed: 0.1µF  [0201]  (hidden comment: GRM033C71A104KE14D)
C192  ValueDisplayed: 0.1µF  [0201]  (hidden comment: GRM033C71A104KE14D)
C193  ValueDisplayed: 0.1µF  [0201]  (hidden comment: GRM033C71A104KE14D)
C194  ValueDisplayed: 0.1µF  [0201]  (hidden comment: GRM033C71A104KE14D)
C195  ValueDisplayed: 0.1µF  [0201]  (hidden comment: GRM033C71A104KE14D)
C196  ValueDisplayed: 0.1µF  [0201]  (hidden comment: GRM033C71A104KE14D)
C343  ValueDisplayed: 4.7pF  [0201]  (hidden comment: GRM0335C1H4R7CA01D)
C344  ValueDisplayed: 0.01µF  [0402]  (hidden comment: GRM155R71H103KA88D)
C345  ValueDisplayed: 4.7pF  [0201]  (hidden comment: GRM0335C1H4R7CA01D)
C347  ValueDisplayed: 4.7pF  [0201]  (hidden comment: GRM0335C1H4R7CA01D)
C348  ValueDisplayed: 0.01µF  [0402]  (hidden comment: GRM155R71H103KA88D)
C349  ValueDisplayed: 4.7pF  [0201]  (hidden comment: GRM0335C1H4R7CA01D)
C351  ValueDisplayed: 4.7pF  [0201]  (hidden comment: GRM0335C1H4R7CA01D)
C352  ValueDisplayed: 0.01µF  [0402]  (hidden comment: GRM155R71H103KA88D)
C353  ValueDisplayed: 4.7pF  [0201]  (hidden comment: GRM0335C1H4R7CA01D)
C355  ValueDisplayed: 4.7pF  [0201]  (hidden comment: GRM0335C1H4R7CA01D)
C356  ValueDisplayed: 0.01µF  [0402]  (hidden comment: GRM155R71H103KA88D)
C357  ValueDisplayed: 4.7pF  [0201]  (hidden comment: GRM0335C1H4R7CA01D)
C359  ValueDisplayed: 4.7pF  [0201]  (hidden comment: GRM0335C1H4R7CA01D)
C360  ValueDisplayed: 0.01µF  [0402]  (hidden comment: GRM155R71H103KA88D)
C361  ValueDisplayed: 4.7pF  [0201]  (hidden comment: GRM0335C1H4R7CA01D)
C363  ValueDisplayed: 4.7pF  [0201]  (hidden comment: GRM0335C1H4R7CA01D)
C364  ValueDisplayed: 0.01µF  [0402]  (hidden comment: GRM155R71H103KA88D)
C365  ValueDisplayed: 4.7pF  [0201]  (hidden comment: GRM0335C1H4R7CA01D)
C367  ValueDisplayed: 4.7pF  [0201]  (hidden comment: GRM0335C1H4R7CA01D)
C368  ValueDisplayed: 0.01µF  [0402]  (hidden comment: GRM155R71H103KA88D)
C369  ValueDisplayed: 4.7pF  [0201]  (hidden comment: GRM0335C1H4R7CA01D)
C371  ValueDisplayed: 4.7pF  [0201]  (hidden comment: GRM0335C1H4R7CA01D)
C372  ValueDisplayed: 0.01µF  [0402]  (hidden comment: GRM155R71H103KA88D)
C373  ValueDisplayed: 4.7pF  [0201]  (hidden comment: GRM0335C1H4R7CA01D)
J8  IP5-04-05.0-L-S-1-TR  [Samtec_IP5-04-05.0-X-S-X-TR]
J9  IP5-04-05.0-L-S-1-TR  [Samtec_IP5-04-05.0-X-S-X-TR]
L51  DNP  ValueDisplayed: 3.3nH  [IND_LQG15H]
L52  ValueDisplayed: 10nH  [IND_LQG15H]  (hidden comment: LQG15HS10NJ02D)
L53  DNP  ValueDisplayed: 15nH  [IND_LQG15H]
L54  DNP  ValueDisplayed: 15nH  [IND_LQG15H]
L55  DNP  ValueDisplayed: 3.3nH  [IND_LQG15H]
L56  ValueDisplayed: 10nH  [IND_LQG15H]  (hidden comment: LQG15HS10NJ02D)
L57  DNP  ValueDisplayed: 15nH  [IND_LQG15H]
L58  DNP  ValueDisplayed: 15nH  [IND_LQG15H]
L59  DNP  ValueDisplayed: 3.3nH  [IND_LQG15H]
L60  ValueDisplayed: 10nH  [IND_LQG15H]  (hidden comment: LQG15HS10NJ02D)
L61  DNP  ValueDisplayed: 15nH  [IND_LQG15H]
L62  DNP  ValueDisplayed: 15nH  [IND_LQG15H]
L63  DNP  ValueDisplayed: 3.3nH  [IND_LQG15H]
L64  ValueDisplayed: 10nH  [IND_LQG15H]  (hidden comment: LQG15HS10NJ02D)
L65  DNP  ValueDisplayed: 15nH  [IND_LQG15H]
L66  DNP  ValueDisplayed: 15nH  [IND_LQG15H]
L67  DNP  ValueDisplayed: 3.3nH  [IND_LQG15H]
L68  ValueDisplayed: 10nH  [IND_LQG15H]  (hidden comment: LQG15HS10NJ02D)
L69  DNP  ValueDisplayed: 15nH  [IND_LQG15H]
L70  DNP  ValueDisplayed: 15nH  [IND_LQG15H]
L71  DNP  ValueDisplayed: 3.3nH  [IND_LQG15H]
L72  ValueDisplayed: 10nH  [IND_LQG15H]  (hidden comment: LQG15HS10NJ02D)
L73  DNP  ValueDisplayed: 15nH  [IND_LQG15H]
L74  DNP  ValueDisplayed: 15nH  [IND_LQG15H]
L75  DNP  ValueDisplayed: 3.3nH  [IND_LQG15H]
L76  ValueDisplayed: 10nH  [IND_LQG15H]  (hidden comment: LQG15HS10NJ02D)
L77  DNP  ValueDisplayed: 15nH  [IND_LQG15H]
L78  DNP  ValueDisplayed: 15nH  [IND_LQG15H]
L79  DNP  ValueDisplayed: 3.3nH  [IND_LQG15H]
L80  ValueDisplayed: 10nH  [IND_LQG15H]  (hidden comment: LQG15HS10NJ02D)
L81  DNP  ValueDisplayed: 15nH  [IND_LQG15H]
L82  DNP  ValueDisplayed: 15nH  [IND_LQG15H]
R213  ValueDisplayed: 0  [0402]  (hidden comment: ERJ-2GE0R00X)
R214  ValueDisplayed: 0  [0201]  (hidden comment: ERJ-1GN0R00C)
R215  ValueDisplayed: 0  [0201]  (hidden comment: ERJ-1GN0R00C)
R216  ValueDisplayed: 0  [0201]  (hidden comment: ERJ-1GN0R00C)
R217  DNP  ValueDisplayed: 0  [0402]
R218  DNP  ValueDisplayed: 0  [0402]
R219  ValueDisplayed: 0  [0201]  (hidden comment: ERJ-1GN0R00C)
R220  ValueDisplayed: 0  [0201]  (hidden comment: ERJ-1GN0R00C)
R221  ValueDisplayed: 0  [0201]  (hidden comment: ERJ-1GN0R00C)
R222  ValueDisplayed: 0  [0402]  (hidden comment: ERJ-2GE0R00X)
R223  ValueDisplayed: 0  [0201]  (hidden comment: ERJ-1GN0R00C)
R224  ValueDisplayed: 0  [0201]  (hidden comment: ERJ-1GN0R00C)
R225  ValueDisplayed: 0  [0201]  (hidden comment: ERJ-1GN0R00C)
R226  DNP  ValueDisplayed: 0  [0402]
R227  DNP  ValueDisplayed: 0  [0402]
R228  ValueDisplayed: 0  [0201]  (hidden comment: ERJ-1GN0R00C)
R229  ValueDisplayed: 0  [0201]  (hidden comment: ERJ-1GN0R00C)
R230  ValueDisplayed: 0  [0201]  (hidden comment: ERJ-1GN0R00C)
R231  ValueDisplayed: 0  [0402]  (hidden comment: ERJ-2GE0R00X)
R232  ValueDisplayed: 0  [0201]  (hidden comment: ERJ-1GN0R00C)
R233  ValueDisplayed: 0  [0201]  (hidden comment: ERJ-1GN0R00C)
R234  ValueDisplayed: 0  [0201]  (hidden comment: ERJ-1GN0R00C)
R235  DNP  ValueDisplayed: 0  [0402]
R236  DNP  ValueDisplayed: 0  [0402]
R237  ValueDisplayed: 0  [0201]  (hidden comment: ERJ-1GN0R00C)
R238  ValueDisplayed: 0  [0201]  (hidden comment: ERJ-1GN0R00C)
R239  ValueDisplayed: 0  [0201]  (hidden comment: ERJ-1GN0R00C)
R240  ValueDisplayed: 0  [0402]  (hidden comment: ERJ-2GE0R00X)
R241  ValueDisplayed: 0  [0201]  (hidden comment: ERJ-1GN0R00C)
R242  ValueDisplayed: 0  [0201]  (hidden comment: ERJ-1GN0R00C)
R243  ValueDisplayed: 0  [0201]  (hidden comment: ERJ-1GN0R00C)
R244  DNP  ValueDisplayed: 0  [0402]
R245  DNP  ValueDisplayed: 0  [0402]
R246  ValueDisplayed: 0  [0201]  (hidden comment: ERJ-1GN0R00C)
R247  ValueDisplayed: 0  [0201]  (hidden comment: ERJ-1GN0R00C)
R248  ValueDisplayed: 0  [0201]  (hidden comment: ERJ-1GN0R00C)
R249  ValueDisplayed: 0  [0402]  (hidden comment: ERJ-2GE0R00X)
R250  ValueDisplayed: 0  [0201]  (hidden comment: ERJ-1GN0R00C)
R251  ValueDisplayed: 0  [0201]  (hidden comment: ERJ-1GN0R00C)
R252  ValueDisplayed: 0  [0201]  (hidden comment: ERJ-1GN0R00C)
R253  DNP  ValueDisplayed: 0  [0402]
R254  DNP  ValueDisplayed: 0  [0402]
R255  ValueDisplayed: 0  [0201]  (hidden comment: ERJ-1GN0R00C)
R256  ValueDisplayed: 0  [0201]  (hidden comment: ERJ-1GN0R00C)
R257  ValueDisplayed: 0  [0201]  (hidden comment: ERJ-1GN0R00C)
R258  ValueDisplayed: 0  [0402]  (hidden comment: ERJ-2GE0R00X)
R259  ValueDisplayed: 0  [0201]  (hidden comment: ERJ-1GN0R00C)
R260  ValueDisplayed: 0  [0201]  (hidden comment: ERJ-1GN0R00C)
R261  ValueDisplayed: 0  [0201]  (hidden comment: ERJ-1GN0R00C)
R262  DNP  ValueDisplayed: 0  [0402]
R263  DNP  ValueDisplayed: 0  [0402]
R264  ValueDisplayed: 0  [0201]  (hidden comment: ERJ-1GN0R00C)
R265  ValueDisplayed: 0  [0201]  (hidden comment: ERJ-1GN0R00C)
R266  ValueDisplayed: 0  [0201]  (hidden comment: ERJ-1GN0R00C)
R267  ValueDisplayed: 0  [0402]  (hidden comment: ERJ-2GE0R00X)
R268  ValueDisplayed: 0  [0201]  (hidden comment: ERJ-1GN0R00C)
R269  ValueDisplayed: 0  [0201]  (hidden comment: ERJ-1GN0R00C)
R270  ValueDisplayed: 0  [0201]  (hidden comment: ERJ-1GN0R00C)
R271  DNP  ValueDisplayed: 0  [0402]
R272  DNP  ValueDisplayed: 0  [0402]
R273  ValueDisplayed: 0  [0201]  (hidden comment: ERJ-1GN0R00C)
R274  ValueDisplayed: 0  [0201]  (hidden comment: ERJ-1GN0R00C)
R275  ValueDisplayed: 0  [0201]  (hidden comment: ERJ-1GN0R00C)
R276  ValueDisplayed: 0  [0402]  (hidden comment: ERJ-2GE0R00X)
R277  ValueDisplayed: 0  [0201]  (hidden comment: ERJ-1GN0R00C)
R278  ValueDisplayed: 0  [0201]  (hidden comment: ERJ-1GN0R00C)
R279  ValueDisplayed: 0  [0201]  (hidden comment: ERJ-1GN0R00C)
R280  DNP  ValueDisplayed: 0  [0402]
R281  DNP  ValueDisplayed: 0  [0402]
R282  ValueDisplayed: 0  [0201]  (hidden comment: ERJ-1GN0R00C)
R283  ValueDisplayed: 0  [0201]  (hidden comment: ERJ-1GN0R00C)
R284  ValueDisplayed: 0  [0201]  (hidden comment: ERJ-1GN0R00C)
R546  DNP  ValueDisplayed: 0  [0402]
T13  1720BL15B0050
T14  1720BL15A0100
T15  1720BL15B0050
T16  1720BL15A0100
T20  1720BL15B0050
T21  1720BL15A0100
T22  1720BL15B0050
T23  1720BL15A0100
T37  1720BL15B0050
T38  1720BL15A0100
T39  1720BL15B0050
T40  1720BL15A0100
T43  1720BL15B0050
T44  1720BL15A0100
T45  1720BL15B0050
T46  1720BL15A0100

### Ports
AFE1_DCO (in), AFE2_AIN1M, AFE2_AIN1P, AFE2_AIN2M, AFE2_AIN2P, AFE2_BIN1M, AFE2_BIN1P, AFE2_BIN2M, AFE2_BIN2P, AFE2_CIN1M, AFE2_CIN1P, AFE2_CIN2M, AFE2_CIN2P, AFE2_DIN1M, AFE2_DIN1P, AFE2_DIN2M, AFE2_DIN2P

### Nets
GND: C189.2 C190.2 C191.2 C192.2 C193.2 C194.2 C195.2 C196.2 J8.P1B J8.P1C J8.P1D J8.P1E J8.P2B J8.P2C J8.P2D J8.P2E J8.P3B J8.P3C J8.P3D J8.P3E J8.P4B J8.P4C J8.P4D J8.P4E J9.P1B J9.P1C J9.P1D J9.P1E J9.P2B J9.P2C J9.P2D J9.P2E J9.P3B J9.P3C J9.P3D J9.P3E J9.P4B J9.P4C J9.P4D J9.P4E L53.2 L54.2 L57.2 L58.2 L61.2 L62.2 L65.2 L66.2 L69.2 L70.2 L73.2 L74.2 L77.2 L78.2 L81.2 L82.2 R217.1 R218.1 R226.1 R227.1 R235.1 R236.1 R244.1 R245.1 R253.1 R254.1 R262.1 R263.1 R271.1 R272.1 R280.1 R281.1 T13.2(GND) T13.5(GND) T14.5(GND) T15.2(GND) T15.5(GND) T16.5(GND) T20.2(GND) T20.5(GND) T21.5(GND) T22.2(GND) T22.5(GND) T23.5(GND) T37.2(GND) T37.5(GND) T38.5(GND) T39.2(GND) T39.5(GND) T40.5(GND) T43.2(GND) T43.5(GND) T44.5(GND) T45.2(GND) T45.5(GND) T46.5(GND)
AFE1_DCO: R546.2 ; port AFE1_DCO
AFE2_A1_IN: J8.P4A R213.1 R217.2
AFE2_A1IN: C344.1 L54.1 T13.1(IN)
AFE2_A2_IN: J8.P3A R249.1 R253.2
AFE2_A2IN: C360.1 L70.1 T15.1(IN)
AFE2_AIN1M: C343.1 ; port AFE2_AIN1M
AFE2_AIN1P: C345.1 ; port AFE2_AIN1P
AFE2_AIN2M: C359.1 ; port AFE2_AIN2M
AFE2_AIN2P: C361.1 ; port AFE2_AIN2P
AFE2_B1_IN: J8.P2A R222.1 R226.2
AFE2_B1IN: C348.1 L58.1 T20.1(IN)
AFE2_B2_IN: J8.P1A R258.1 R262.2 R546.1
AFE2_B2IN: C364.1 L74.1 T22.1(IN)
AFE2_BIN1M: C347.1 ; port AFE2_BIN1M
AFE2_BIN1P: C349.1 ; port AFE2_BIN1P
AFE2_BIN2M: C363.1 ; port AFE2_BIN2M
AFE2_BIN2P: C365.1 ; port AFE2_BIN2P
AFE2_C1_IN: J9.P1A R231.1 R235.2
AFE2_C1IN: C352.1 L62.1 T37.1(IN)
AFE2_C2_IN: J9.P2A R267.1 R271.2
AFE2_C2IN: C368.1 L78.1 T39.1(IN)
AFE2_CIN1M: C353.1 ; port AFE2_CIN1M
AFE2_CIN1P: C351.1 ; port AFE2_CIN1P
AFE2_CIN2M: C369.1 ; port AFE2_CIN2M
AFE2_CIN2P: C367.1 ; port AFE2_CIN2P
AFE2_D1_IN: J9.P3A R240.1 R244.2
AFE2_D1IN: C356.1 L66.1 T43.1(IN)
AFE2_D2_IN: J9.P4A R276.1 R280.2
AFE2_D2IN: C372.1 L82.1 T45.1(IN)
AFE2_DIN1M: C357.1 ; port AFE2_DIN1M
AFE2_DIN1P: C355.1 ; port AFE2_DIN1P
AFE2_DIN2M: C373.1 ; port AFE2_DIN2M
AFE2_DIN2P: C371.1 ; port AFE2_DIN2P
NetC189_1: C189.1 T13.3(OUT1) T14.2(GND)
NetC190_1: C190.1 T15.3(OUT1) T16.2(GND)
NetC191_1: C191.1 T20.3(OUT1) T21.2(GND)
NetC192_1: C192.1 T22.3(OUT1) T23.2(GND)
NetC193_1: C193.1 T37.3(OUT1) T38.2(GND)
NetC194_1: C194.1 T39.3(OUT1) T40.2(GND)
NetC195_1: C195.1 T43.3(OUT1) T44.2(GND)
NetC196_1: C196.1 T45.3(OUT1) T46.2(GND)
NetC343_2: C343.2 R216.2
NetC344_2: C344.2 L53.1 R213.2 R218.2
NetC345_2: C345.2 R221.2
NetC347_2: C347.2 R225.2
NetC348_2: C348.2 L57.1 R222.2 R227.2
NetC349_2: C349.2 R230.2
NetC351_2: C351.2 R234.2
NetC352_2: C352.2 L61.1 R231.2 R236.2
NetC353_2: C353.2 R239.2
NetC355_2: C355.2 R243.2
NetC356_2: C356.2 L65.1 R240.2 R245.2
NetC357_2: C357.2 R248.2
NetC359_2: C359.2 R252.2
NetC360_2: C360.2 L69.1 R249.2 R254.2
NetC361_2: C361.2 R257.2
NetC363_2: C363.2 R261.2
NetC364_2: C364.2 L73.1 R258.2 R263.2
NetC365_2: C365.2 R266.2
NetC367_2: C367.2 R270.2
NetC368_2: C368.2 L77.1 R267.2 R272.2
NetC369_2: C369.2 R275.2
NetC371_2: C371.2 R279.2
NetC372_2: C372.2 L81.1 R276.2 R281.2
NetC373_2: C373.2 R284.2
NetL51_1: L51.1 R219.2 R220.1
NetL51_2: L51.2 R214.2 R215.1
NetL52_1: L52.1 R220.2 R221.1
NetL52_2: L52.2 R215.2 R216.1
NetL55_1: L55.1 R228.2 R229.1
NetL55_2: L55.2 R223.2 R224.1
NetL56_1: L56.1 R229.2 R230.1
NetL56_2: L56.2 R224.2 R225.1
NetL59_1: L59.1 R237.2 R238.1
NetL59_2: L59.2 R232.2 R233.1
NetL60_1: L60.1 R238.2 R239.1
NetL60_2: L60.2 R233.2 R234.1
NetL63_1: L63.1 R246.2 R247.1
NetL63_2: L63.2 R241.2 R242.1
NetL64_1: L64.1 R247.2 R248.1
NetL64_2: L64.2 R242.2 R243.1
NetL67_1: L67.1 R255.2 R256.1
NetL67_2: L67.2 R250.2 R251.1
NetL68_1: L68.1 R256.2 R257.1
NetL68_2: L68.2 R251.2 R252.1
NetL71_1: L71.1 R264.2 R265.1
NetL71_2: L71.2 R259.2 R260.1
NetL72_1: L72.1 R265.2 R266.1
NetL72_2: L72.2 R260.2 R261.1
NetL75_1: L75.1 R273.2 R274.1
NetL75_2: L75.2 R268.2 R269.1
NetL76_1: L76.1 R274.2 R275.1
NetL76_2: L76.2 R269.2 R270.1
NetL79_1: L79.1 R282.2 R283.1
NetL79_2: L79.2 R277.2 R278.1
NetL80_1: L80.1 R283.2 R284.1
NetL80_2: L80.2 R278.2 R279.1
NetR214_1: R214.1 T14.3(OUT1)
NetR219_1: R219.1 T14.4(OUT2)
NetR223_1: R223.1 T21.3(OUT1)
NetR228_1: R228.1 T21.4(OUT2)
NetR232_1: R232.1 T38.3(OUT1)
NetR237_1: R237.1 T38.4(OUT2)
NetR241_1: R241.1 T44.3(OUT1)
NetR246_1: R246.1 T44.4(OUT2)
NetR250_1: R250.1 T16.3(OUT1)
NetR255_1: R255.1 T16.4(OUT2)
NetR259_1: R259.1 T23.3(OUT1)
NetR264_1: R264.1 T23.4(OUT2)
NetR268_1: R268.1 T40.3(OUT1)
NetR273_1: R273.1 T40.4(OUT2)
NetR277_1: R277.1 T46.3(OUT1)
NetR282_1: R282.1 T46.4(OUT2)
NetT13_4: T13.4(OUT2) T14.1(IN)
NetT15_4: T15.4(OUT2) T16.1(IN)
NetT20_4: T20.4(OUT2) T21.1(IN)
NetT22_4: T22.4(OUT2) T23.1(IN)
NetT37_4: T37.4(OUT2) T38.1(IN)
NetT39_4: T39.4(OUT2) T40.1(IN)
NetT43_4: T43.4(OUT2) T44.1(IN)
NetT45_4: T45.4(OUT2) T46.1(IN)

Not connected (* = marked no-connect by the designer): T13 6(NC)*; T14 6(NC)*; T15 6(NC)*; T16 6(NC)*; T20 6(NC)*; T21 6(NC)*; T22 6(NC)*; T23 6(NC)*; T37 6(NC)*; T38 6(NC)*; T39 6(NC)*; T40 6(NC)*; T43 6(NC)*; T44 6(NC)*; T45 6(NC)*; T46 6(NC)*

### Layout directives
differential pair: AFE2_AIN1M, AFE2_AIN1P, AFE2_AIN2M, AFE2_AIN2P, AFE2_BIN1M, AFE2_BIN1P, AFE2_BIN2M, AFE2_BIN2P, AFE2_CIN1M, AFE2_CIN1P, AFE2_CIN2M, AFE2_CIN2P, AFE2_DIN1M, AFE2_DIN1P, AFE2_DIN2M, AFE2_DIN2P

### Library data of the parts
C189-C196 = GRM033C71A104KE14D: as C342 on sheet AFE2-PROGRAMMING INTERFACE
C343 C345 C347 C349 C351 C353 C355 C357 C359 C361 C363 C365 C367 C369 C371 C373 = GRM0335C1H4R7CA01D: CAP, CERM, 4.7 pF, 50 V,+/- 5%, C0G/NP0, 0201; Manufacturer: MuRata; Polarized: N; CompType: Capacitor; Value: 4.7pF; U/M: EA; Cap_F: 0.0000000000047; Tolerance_%: 5; Value1: Unknown; VDC_V: 50; Value2: 50V; TaMin_C: -55; TaMax_C: 125; SizeArea_mm2: 0.18; SizeAreaWB_mm2: 2.08; SizeX_mm: 0.6; SizeY_mm: 0.3; SizeZ_mm: 0.26; AEC Category: Q200
C344 C348 C352 C356 C360 C364 C368 C372 = GRM155R71H103KA88D: CAP, CERM, 0.01 µF, 50 V,+/- 10%, X7R, 0402; Manufacturer: MuRata; Polarized: N; CompType: Capacitor; Value: 0.01uF; U/M: EA; Cap_F: 0.00000001; Tolerance_%: 10; Value1: Unknown; VDC_V: 50; Value2: 50V; TaMin_C: -55; TaMax_C: 125; SizeArea_mm2: 0.5; SizeAreaWB_mm2: 3; SizeX_mm: 1; SizeZ_mm: 0.6; AEC Category: Q200; Green_Lifecycle: Active; Green_REACh: Passed
J8 J9 = CMP-0084573-1: Plug, 4 Ports, TH; Manufacturer: Samtec; Gender: Male; Voltage_V: 200V; ContactFinish: Gold; Row_Count: 1; Current_A: 2.36A; Cert_UL: Y
L51 L55 L59 L63 L67 L71 L75 L79 = LQG15HS3N3S02D: Inductor, Multilayer, Air Core, 3.3 nH, 0.3 A, 0.17 ohm, SMD; Manufacturer: MuRata; Value: 3.3nH; Ind_H: 3.3E-9; Imax_A: 0.3; Irms: 0.3A @ C rise; Isat: 0.3A @ % inductance drop; DCR_ohm: 0.17; Value2: 0.3A; SizeAreaWB_mm2: 3; SizeArea_mm2: 0.5; SizeX_mm: 1; SizeZ_mm: 0.55; AEC Category: Q200; Green_Lifecycle: Active; Green_REACh: Passed
L52 L56 L60 L64 L68 L72 L76 L80 = LQG15HS10NJ02D: Inductor, Multilayer, Air Core, 10 nH, 0.3 A, 0.26 ohm, SMD; Manufacturer: MuRata; Value: 10nH; Ind_H: 10.0E-9; Imax_A: 0.3; Irms: 0.3A @ C rise; Isat: 0.3A @ % inductance drop; DCR_ohm: 0.26; Value2: 0.3A; SizeAreaWB_mm2: 3; SizeArea_mm2: 0.5; SizeX_mm: 1; SizeZ_mm: 0.55; AEC Category: Q200; Green_Lifecycle: Active; Green_REACh: Passed
L53 L54 L57 L58 L61 L62 L65 L66 L69 L70 L73 L74 L77 L78 L81 L82 = LQG15HS15NJ02D: Inductor, Multilayer, Air Core, 15 nH, 0.3 A, 0.32 ohm, SMD; Manufacturer: MuRata; Value: 15nH; Ind_H: 15.0E-9; Imax_A: 0.3; Irms: 0.3A @ C rise; Isat: 0.3A @ % inductance drop; DCR_ohm: 0.32; Value2: 0.3A; SizeAreaWB_mm2: 3; SizeArea_mm2: 0.5; SizeX_mm: 1; SizeZ_mm: 0.55; AEC Category: Q200; Green_Lifecycle: Active; Green_REACh: Passed
R213 R217 R218 R222 R226 R227 R231 R235 R236 R240 R244 R245 R249 R253 R254 R258 R262 R263 R267 R271 R272 R276 R280 R281 R546 = ERJ-2GE0R00X: RES, 0, 5%, 0.063 W, 0402; Manufacturer: Panasonic; CompType: Resistor; Value: 0; Value_Code: 0000; Tolerance_%: 5; Power_W: 0.063; Value2: 0.063W; VDC_V: 50; TempCo: 600 ppm/C; SizeArea_mm2: 0.5; SizeX_mm: 1; SizeZ_mm: 0.6; EIA_Code: E24; U/M: EA; AEC Category: Q200; Green_Lifecycle: Active; Green_REACh: Passed
R214-R216 R219-R221 R223-R225 R228-R230 R232-R234 R237-R239 R241-R243 R246-R248 R250-R252 R255-R257 R259-R261 R264-R266 R268-R270 R273-R275 R277-R279 R282-R284 = ERJ-1GN0R00C: RES, 0, 5%, 0.05 W, AEC-Q200 Grade 0, 0201; Manufacturer: Panasonic; CompType: Resistor; Value: 0; Value_Code: 0000; Tolerance_%: 5; Power_W: 0.05; Value2: 0.05W; TempCo: ppm/C; SizeArea_mm2: 0.18; SizeX_mm: 0.6; SizeY_mm: 0.3; SizeZ_mm: 0.26; EIA_Code: E24; U/M: EA; AEC Category: Q200; AEC Qualified: Y
T13 T15 T20 T22 T37 T39 T43 T45 = 1720BL15B0050: BALUN 625MHZ-2.8GHZ 50/50 0805; PartNumber: 1720BL15B0050E; Manufacturer: Johanson Technology Inc.
T14 T16 T21 T23 T38 T40 T44 T46 = 1720BL15A0100: BALUN 625MHZ-2.8GHZ 50/100 0805; PartNumber: 1720BL15A0100E; Manufacturer: Johanson Technology Inc.

## Sheet AFE2-TX-OUTPUTS.SchDoc
size 431 x 279 mm; Date: Not shown in title block; ApprovedBy: Not shown in title block; CheckedBy: Not shown in title block; Author: Not shown in title block; CompanyName: Not shown in title block; DrawnBy: Avinash N; Engineer: Not shown in title block; Organization: Not shown in title block; Address1: Not shown in title block; Address2: Not shown in title block; Address3: Not shown in title block; Address4: Not shown in title block; DocumentNumber: 1; Revision: Use project parameter SCH_Rev; SheetNumber: 17; SheetTotal: 32; PageSetup: Record=PageOptions¦CenterHorizontal=True¦CenterVertical=True¦PrintScale=1.00¦XCorrection=1.00¦YCorrection=1.00¦PrintKind=0¦BorderSize=5000000¦LeftOffset=0¦BottomOffset=0¦Orientation=2¦PaperLength=1000¦PaperWidth=1000¦Scale=100¦PaperSource=15¦PrintQuality=600¦MediaType=1¦DitherType=10¦PaperKind=Letter¦PrintScaleMode=1
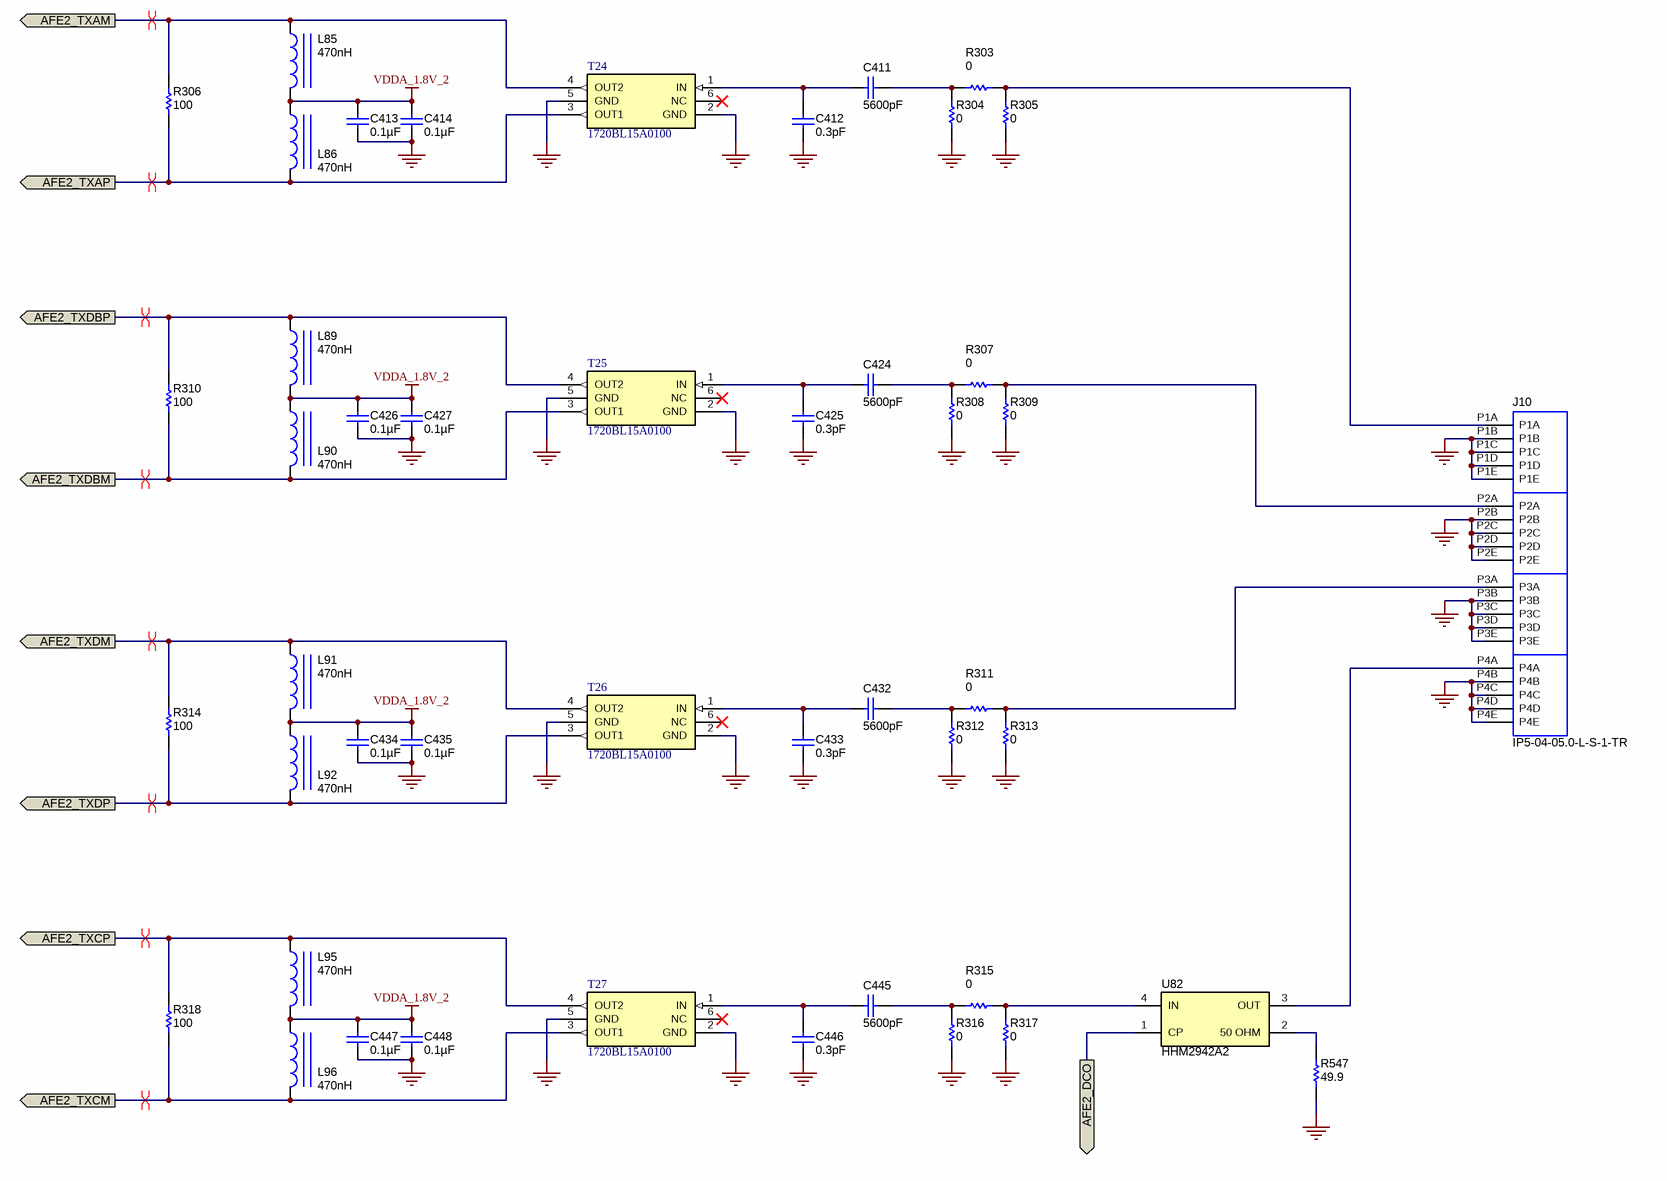
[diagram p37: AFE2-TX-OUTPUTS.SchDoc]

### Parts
C411  ValueDisplayed: 5600pF  [0402]  (hidden comment: GRM155R71H562KA88D)
C412  ValueDisplayed: 0.3pF  [0402]  (hidden comment: 500R07S0R3BV4T)
C413  ValueDisplayed: 0.1µF  [0201]  (hidden comment: GRM033C71A104KE14D)
C414  ValueDisplayed: 0.1µF  [0201]  (hidden comment: GRM033C71A104KE14D)
C424  ValueDisplayed: 5600pF  [0402]  (hidden comment: GRM155R71H562KA88D)
C425  ValueDisplayed: 0.3pF  [0402]  (hidden comment: 500R07S0R3BV4T)
C426  ValueDisplayed: 0.1µF  [0201]  (hidden comment: GRM033C71A104KE14D)
C427  ValueDisplayed: 0.1µF  [0201]  (hidden comment: GRM033C71A104KE14D)
C432  ValueDisplayed: 5600pF  [0402]  (hidden comment: GRM155R71H562KA88D)
C433  ValueDisplayed: 0.3pF  [0402]  (hidden comment: 500R07S0R3BV4T)
C434  ValueDisplayed: 0.1µF  [0201]  (hidden comment: GRM033C71A104KE14D)
C435  ValueDisplayed: 0.1µF  [0201]  (hidden comment: GRM033C71A104KE14D)
C445  ValueDisplayed: 5600pF  [0402]  (hidden comment: GRM155R71H562KA88D)
C446  ValueDisplayed: 0.3pF  [0402]  (hidden comment: 500R07S0R3BV4T)
C447  ValueDisplayed: 0.1µF  [0201]  (hidden comment: GRM033C71A104KE14D)
C448  ValueDisplayed: 0.1µF  [0201]  (hidden comment: GRM033C71A104KE14D)
J10  IP5-04-05.0-L-S-1-TR  [Samtec_IP5-04-05.0-X-S-X-TR]
L85  ValueDisplayed: 470nH  [DFE160808S]  (hidden comment: DFE160808S-R47M=P2)
L86  ValueDisplayed: 470nH  [DFE160808S]  (hidden comment: DFE160808S-R47M=P2)
L89  ValueDisplayed: 470nH  [DFE160808S]  (hidden comment: DFE160808S-R47M=P2)
L90  ValueDisplayed: 470nH  [DFE160808S]  (hidden comment: DFE160808S-R47M=P2)
L91  ValueDisplayed: 470nH  [DFE160808S]  (hidden comment: DFE160808S-R47M=P2)
L92  ValueDisplayed: 470nH  [DFE160808S]  (hidden comment: DFE160808S-R47M=P2)
L95  ValueDisplayed: 470nH  [DFE160808S]  (hidden comment: DFE160808S-R47M=P2)
L96  ValueDisplayed: 470nH  [DFE160808S]  (hidden comment: DFE160808S-R47M=P2)
R303  ValueDisplayed: 0  [0402]  (hidden comment: ERJ-2GE0R00X)
R304  ValueDisplayed: 0  [0402]  (hidden comment: ERJ-2GE0R00X)
R305  ValueDisplayed: 0  [0402]  (hidden comment: ERJ-2GE0R00X)
R306  ValueDisplayed: 100  [0402]  (hidden comment: ERJ-2RKF1000X)
R307  ValueDisplayed: 0  [0402]  (hidden comment: ERJ-2GE0R00X)
R308  ValueDisplayed: 0  [0402]  (hidden comment: ERJ-2GE0R00X)
R309  ValueDisplayed: 0  [0402]  (hidden comment: ERJ-2GE0R00X)
R310  ValueDisplayed: 100  [0402]  (hidden comment: ERJ-2RKF1000X)
R311  ValueDisplayed: 0  [0402]  (hidden comment: ERJ-2GE0R00X)
R312  ValueDisplayed: 0  [0402]  (hidden comment: ERJ-2GE0R00X)
R313  ValueDisplayed: 0  [0402]  (hidden comment: ERJ-2GE0R00X)
R314  ValueDisplayed: 100  [0402]  (hidden comment: ERJ-2RKF1000X)
R315  ValueDisplayed: 0  [0402]  (hidden comment: ERJ-2GE0R00X)
R316  ValueDisplayed: 0  [0402]  (hidden comment: ERJ-2GE0R00X)
R317  ValueDisplayed: 0  [0402]  (hidden comment: ERJ-2GE0R00X)
R318  ValueDisplayed: 100  [0402]  (hidden comment: ERJ-2RKF1000X)
R547  ValueDisplayed: 49.9  [0402]  (hidden comment: ERJ-2RKF49R9X)
T24  1720BL15A0100
T25  1720BL15A0100
T26  1720BL15A0100
T27  1720BL15A0100
U82  HHM2942A2  [HHM2942A2]

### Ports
AFE2_DCO (out), AFE2_TXAM (out), AFE2_TXAP (out), AFE2_TXCM (out), AFE2_TXCP (out), AFE2_TXDBM (out), AFE2_TXDBP (out), AFE2_TXDM (out), AFE2_TXDP (out)

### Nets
GND: C412.2 C413.1 C414.1 C425.2 C426.1 C427.1 C433.2 C434.1 C435.1 C446.2 C447.1 C448.1 J10.P1B J10.P1C J10.P1D J10.P1E J10.P2B J10.P2C J10.P2D J10.P2E J10.P3B J10.P3C J10.P3D J10.P3E J10.P4B J10.P4C J10.P4D J10.P4E R304.1 R305.1 R308.1 R309.1 R312.1 R313.1 R316.1 R317.1 R547.1 T24.2(GND) T24.5(GND) T25.2(GND) T25.5(GND) T26.2(GND) T26.5(GND) T27.2(GND) T27.5(GND)
VDDA_1.8V_2: C413.2 C414.2 C426.2 C427.2 C434.2 C435.2 C447.2 C448.2 L85.2 L86.1 L89.2 L90.1 L91.2 L92.1 L95.2 L96.1
AFE2_DCO: U82.1(CP) ; port AFE2_DCO
AFE2_TXAM: L85.1 R306.2 T24.4(OUT2) ; port AFE2_TXAM
AFE2_TXAP: L86.2 R306.1 T24.3(OUT1) ; port AFE2_TXAP
AFE2_TXCM: L96.2 R318.1 T27.3(OUT1) ; port AFE2_TXCM
AFE2_TXCP: L95.1 R318.2 T27.4(OUT2) ; port AFE2_TXCP
AFE2_TXDBM: L90.2 R310.1 T25.3(OUT1) ; port AFE2_TXDBM
AFE2_TXDBP: L89.1 R310.2 T25.4(OUT2) ; port AFE2_TXDBP
AFE2_TXDM: L91.1 R314.2 T26.4(OUT2) ; port AFE2_TXDM
AFE2_TXDP: L92.2 R314.1 T26.3(OUT1) ; port AFE2_TXDP
NetC411_1: C411.1 C412.1 T24.1(IN)
NetC411_2: C411.2 R303.1 R304.2
NetC424_1: C424.1 C425.1 T25.1(IN)
NetC424_2: C424.2 R307.1 R308.2
NetC432_1: C432.1 C433.1 T26.1(IN)
NetC432_2: C432.2 R311.1 R312.2
NetC445_1: C445.1 C446.1 T27.1(IN)
NetC445_2: C445.2 R315.1 R316.2
NetJ10_P1A: J10.P1A R303.2 R305.2
NetJ10_P2A: J10.P2A R307.2 R309.2
NetJ10_P3A: J10.P3A R311.2 R313.2
NetJ10_P4A: J10.P4A U82.3(OUT)
NetR315_2: R315.2 R317.2 U82.4(IN)
NetR547_2: R547.2 U82.2(50_OHM)

Not connected (* = marked no-connect by the designer): T24 6(NC)*; T25 6(NC)*; T26 6(NC)*; T27 6(NC)*

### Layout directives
differential pair: AFE2_TXAM, AFE2_TXAP, AFE2_TXCM, AFE2_TXCP, AFE2_TXDBM, AFE2_TXDBP, AFE2_TXDM, AFE2_TXDP

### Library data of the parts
C411 C424 C432 C445 = GRM155R71H562KA88D: CAP, CERM, 5600 pF, 50 V,+/- 10%, X7R, 0402; Manufacturer: MuRata; Polarized: N; CompType: Capacitor; Value: 5600pF; U/M: EA; Cap_F: 0.0000000056; Tolerance_%: 10; Value1: Unknown; VDC_V: 50; Value2: 50V; TaMin_C: -55; TaMax_C: 125; SizeArea_mm2: 0.5; SizeAreaWB_mm2: 3; SizeX_mm: 1; SizeZ_mm: 0.6; AEC Category: Q200; Green_Lifecycle: Active; Green_REACh: Passed
C412 C425 C433 C446 = 500R07S0R3BV4T: CAP, CERM, 0.3 pF, 50 V,+/- 30%, C0G/NP0, 0402; Manufacturer: Johanson Technology; Polarized: N; CompType: Capacitor; Value: 0.3pF; U/M: EA; Cap_F: 0.0000000000003; Tolerance_%: 30; Value1: Unknown; VDC_V: 50; Value2: 50V; TaMin_C: -55; TaMax_C: 125; SizeArea_mm2: 0.5; SizeAreaWB_mm2: 3; SizeX_mm: 1; SizeZ_mm: 0.6; AEC Category: Q200
C413 C414 C426 C427 C434 C435 C447 C448 = GRM033C71A104KE14D: as C342 on sheet AFE2-PROGRAMMING INTERFACE
J10 = CMP-0084573-1: as J8 on sheet AFE2-RX-INPUTS
L85 L86 L89-L92 L95 L96 = DFE160808S-R47M=P2: Inductor, Shielded, Metal Composite, 470 nH, 2.4 A, 0.064 ohm, SMD; Manufacturer: MuRata; Value: 470nH; Ind_H: 470.0E-9; Imax_A: 2.4; Irms: 2.4A @ 40C rise; Isat: 3.1A @ 30% inductance drop; DCR_ohm: 0.064; Value2: 2.4A; SizeAreaWB_mm2: 4.68; SizeArea_mm2: 1.28; SizeX_mm: 1.6; SizeY_mm: 0.8; AEC Category: Q200; AEC Qualified: N; Green_Lifecycle: Not Set; Green_REACh: Incomplete
R303-R305 R307-R309 R311-R313 R315-R317 = ERJ-2GE0R00X: as R213 on sheet AFE2-RX-INPUTS
R306 R310 R314 R318 = ERJ-2RKF1000X: RES, 100, 1%, 0.1 W, 0402; Manufacturer: Panasonic; CompType: Resistor; Value: 100; Value_Code: 100R; Tolerance_%: 1; Power_W: 0.1; Value2: 0.1W; VDC_V: 50; TempCo: 100 ppm/C; SizeArea_mm2: 0.5; SizeZ_mm: 0.6; EIA_Code: E96; U/M: EA; AEC Category: Q200; Green_Lifecycle: Active; Green_REACh: Passed
R547 = ERJ-2RKF49R9X: as R432-R435 on sheet AFE2-GPIOs
T24-T27 = 1720BL15A0100: as T14 on sheet AFE2-RX-INPUTS
U82 = CMP-0079338-2: Multilayer Directional Coupler For 2400-2500MHz / 4900-5850MHz, SMD-4; Manufacturer: TDK; SizeZ_mm: 0.4; SizeArea_mm2: 0.5; SizeAreaWB_mm2: 3; SizeY_mm: 1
